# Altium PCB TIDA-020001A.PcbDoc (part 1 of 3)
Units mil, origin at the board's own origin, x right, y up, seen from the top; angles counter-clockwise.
Board outline 11050 x 5518 mil, 4 copper layers (Top Layer, PWR, GND, Bottom Layer), stack 61.434 mil thick; 283 components, 210 nets, 883 pads, 1184 vias.
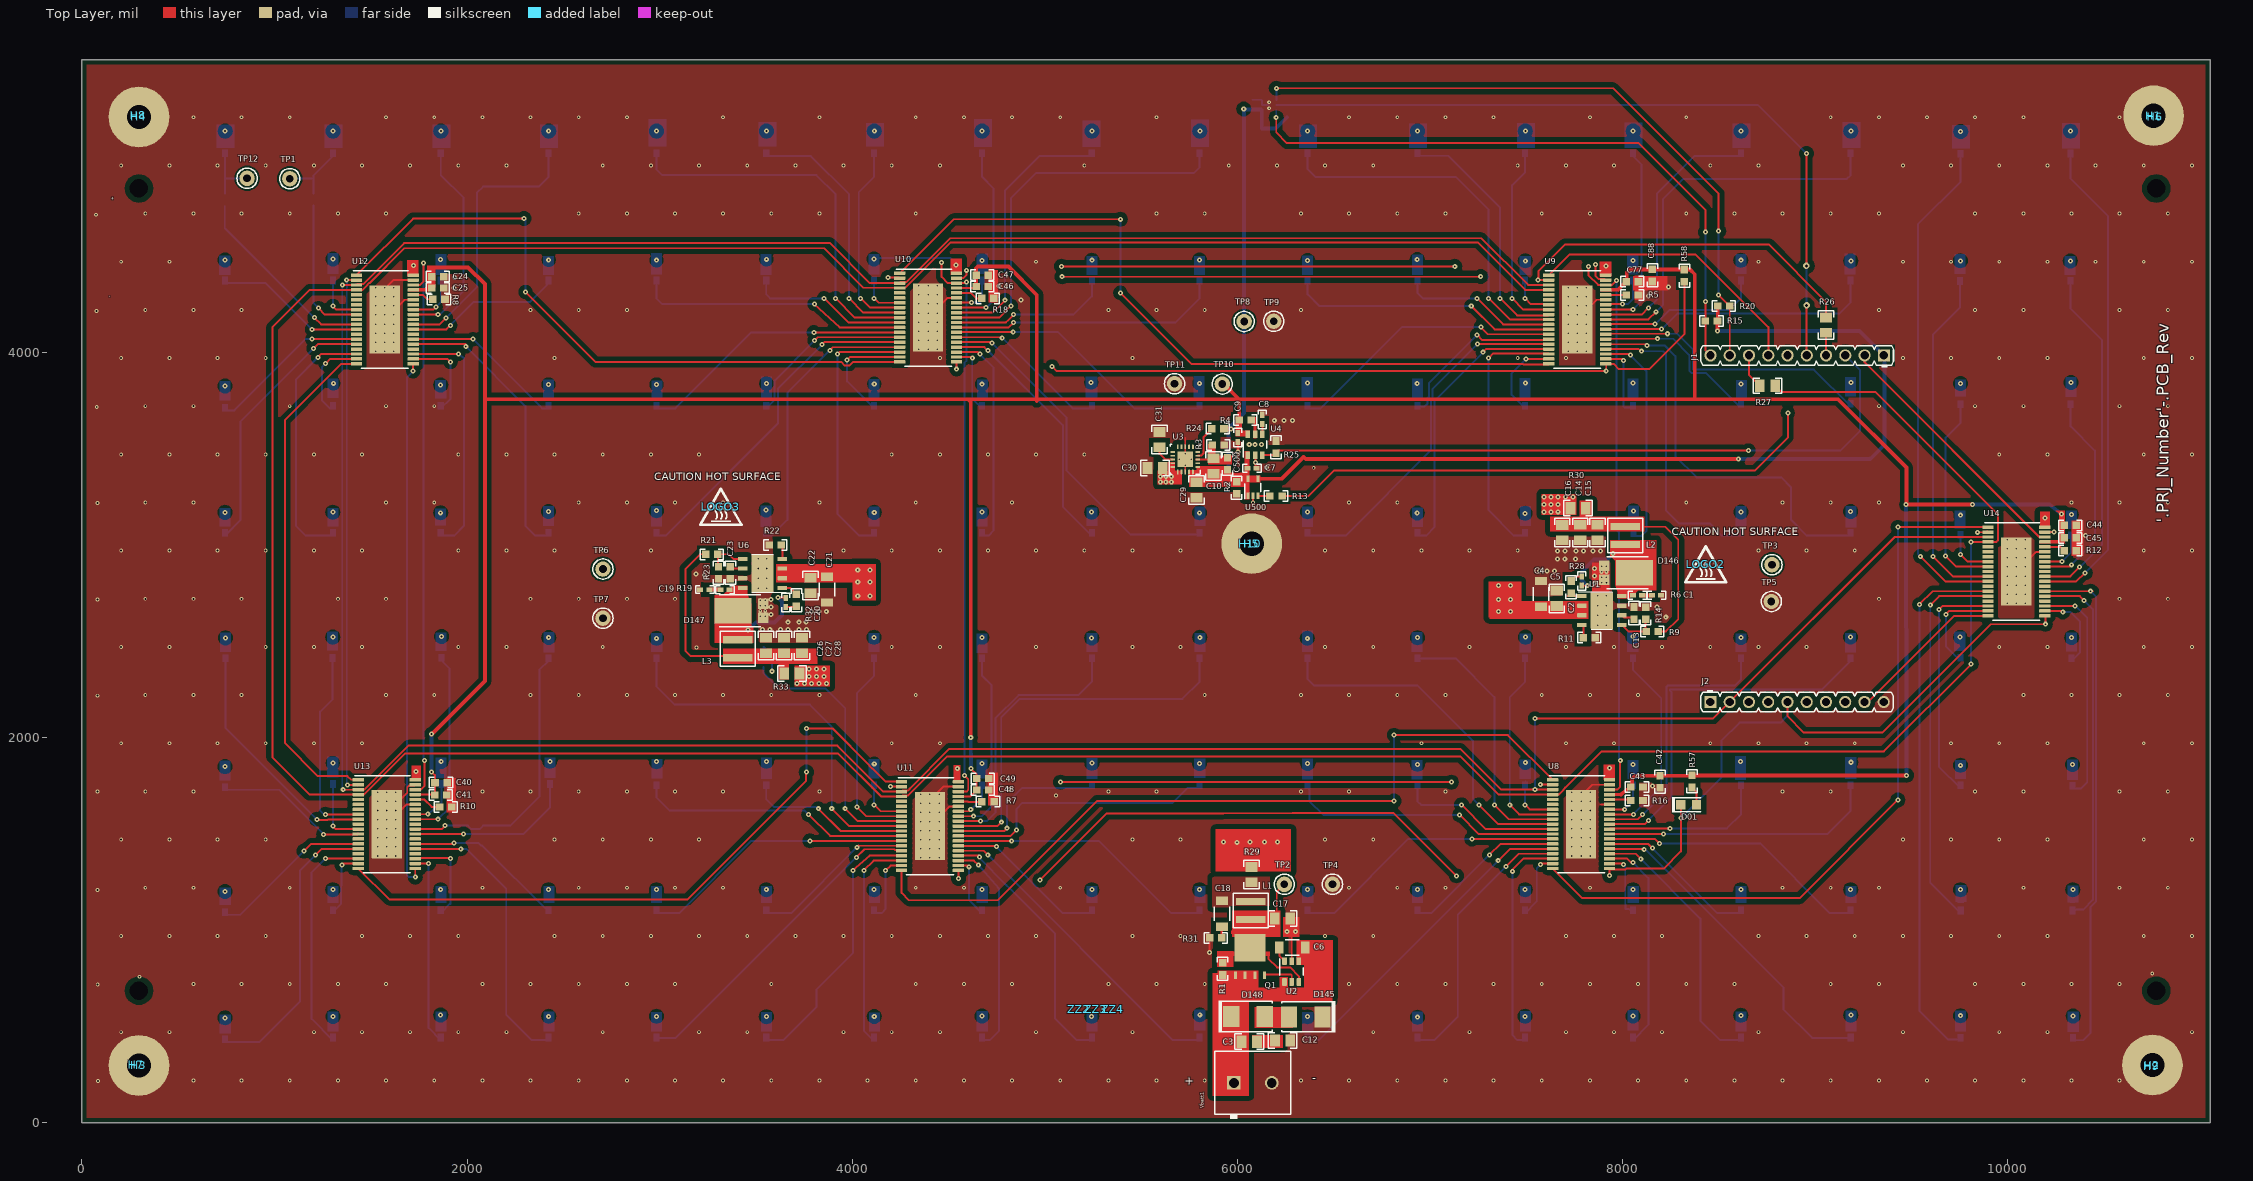
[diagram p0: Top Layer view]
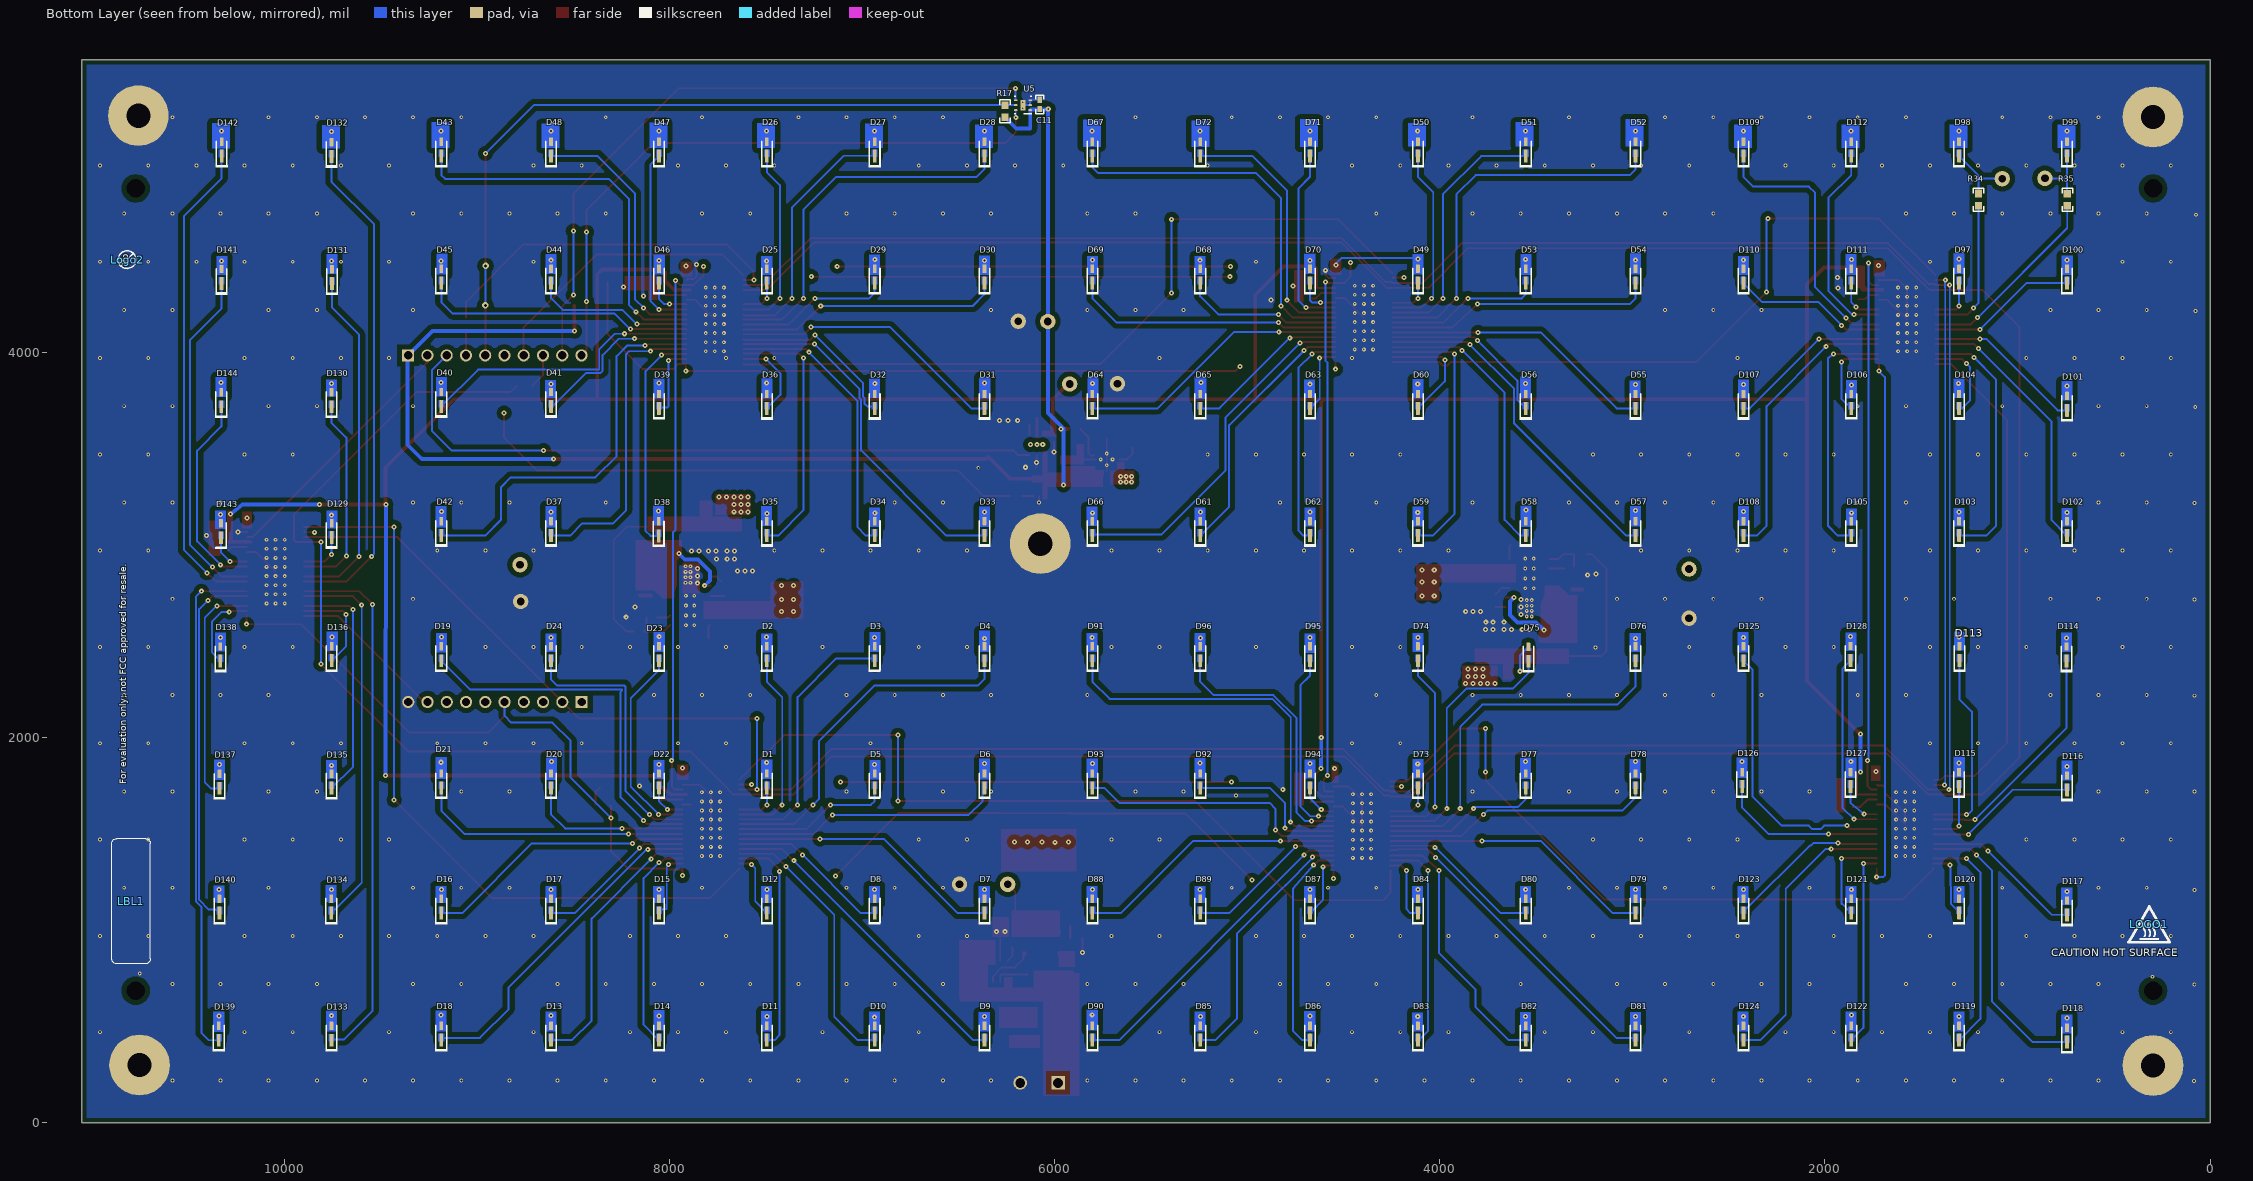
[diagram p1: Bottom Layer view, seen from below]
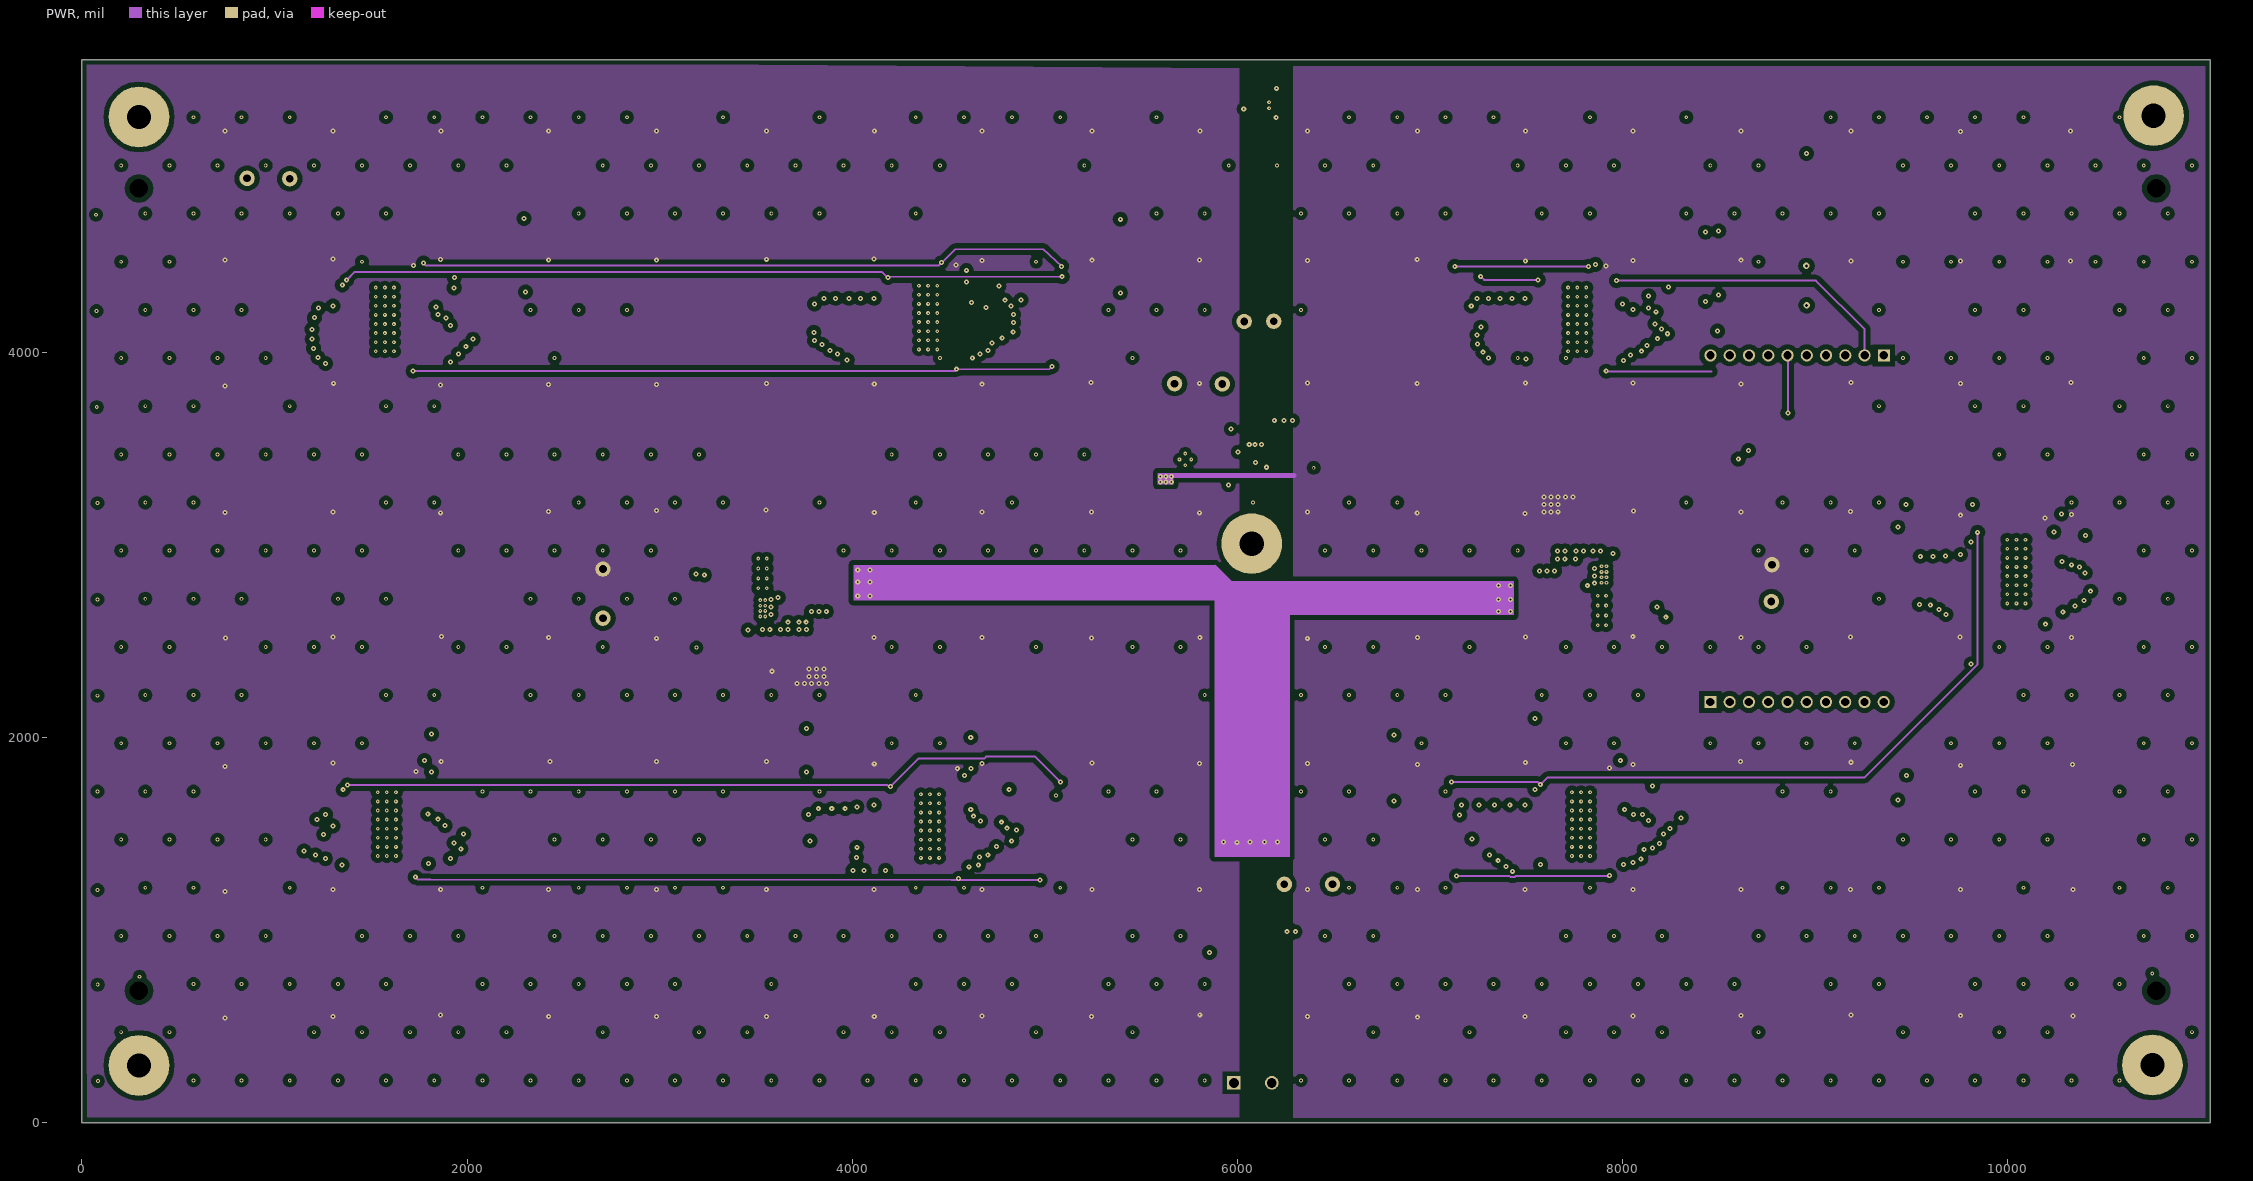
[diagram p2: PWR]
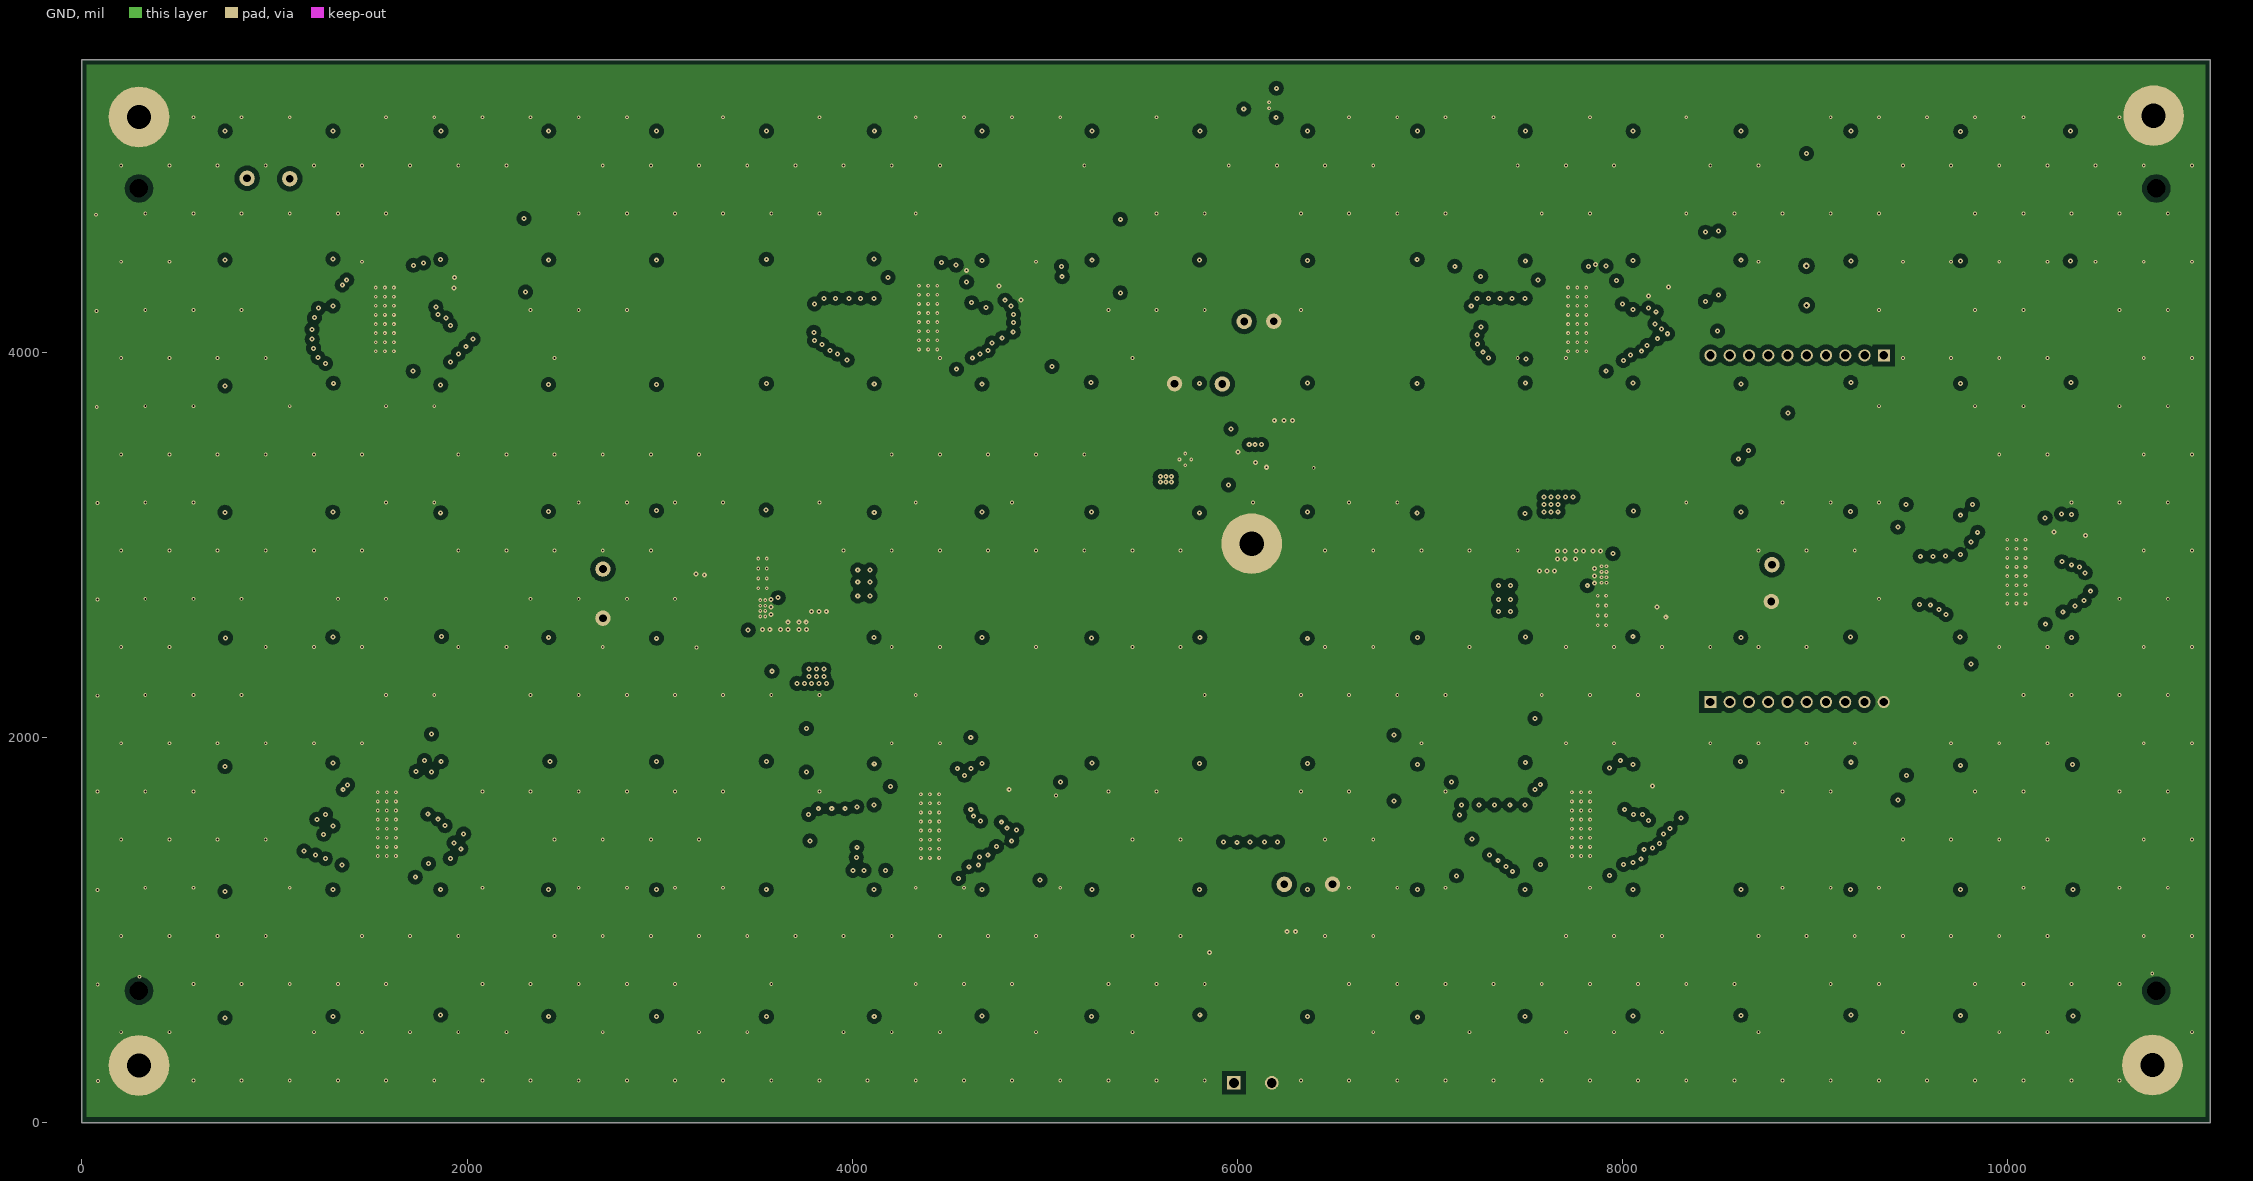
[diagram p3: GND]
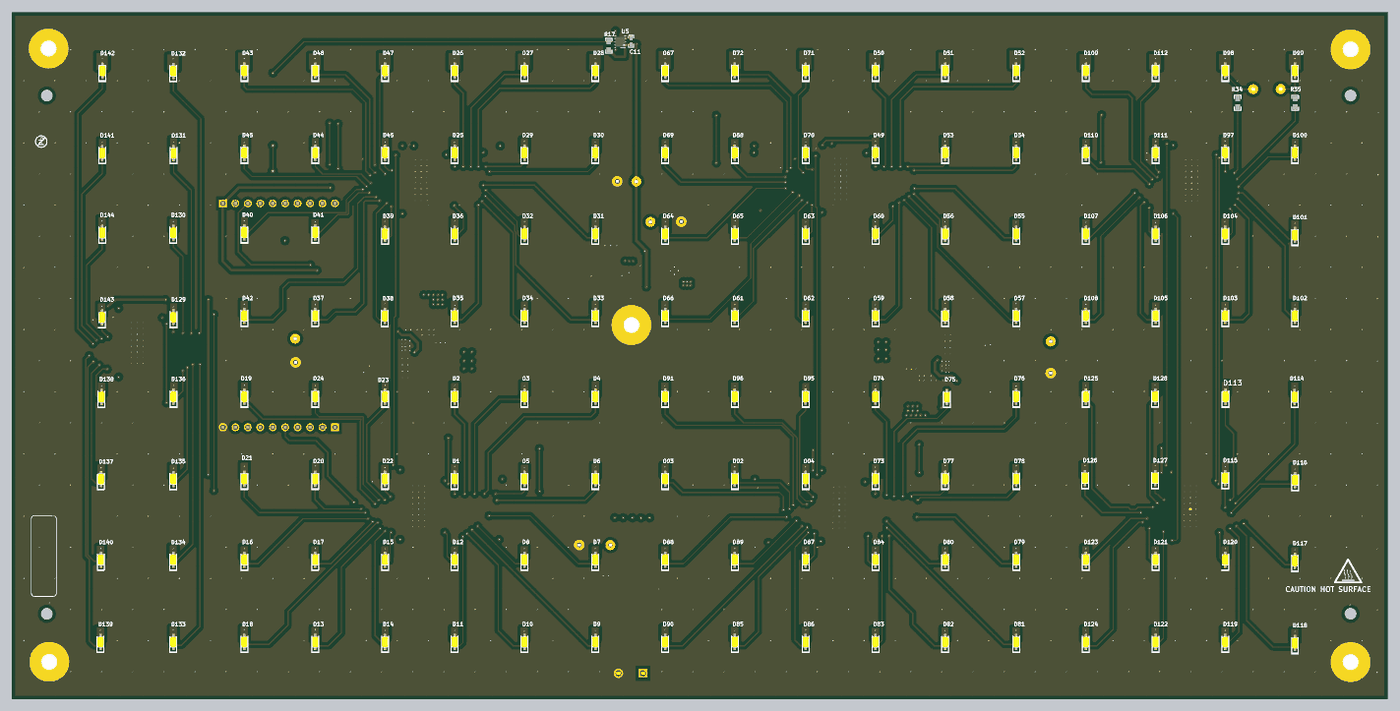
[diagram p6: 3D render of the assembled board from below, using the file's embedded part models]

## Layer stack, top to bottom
Top Solder: solder mask 0.4, Solder Resist, Dk 3.5
Top Layer: signal copper 1.4
Dielectric1: prepreg 18.6, 370HR, Dk 4.2
PWR: signal copper 1.417
Dielectric 2: core 18.6, 370HR, Dk 4.2
GND: signal copper 1.417
Dielectric 3: prepreg 18.6, 370HR, Dk 4.2
Bottom Layer: signal copper 1.4
Bottom Solder: solder mask 0.4, Solder Resist, Dk 3.5

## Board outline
0,0 11050,0 11050,5518 0,5518

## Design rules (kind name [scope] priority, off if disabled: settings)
AcuteAngle [All] p1: minimum=4.40000000000000E+0001 checktracksonly=FALSE
AssemblyTestPointUsage [All] p1: valid=2
BoardOutlineClearance BoardOutlineClearance_MountingHoles [OnCopper and InComponentClass('Mounting Holes')] p1: gap=40
BoardOutlineClearance BoardOutlineClearance_Poly [OnCopper and IsPoly] p2: gap=25
BoardOutlineClearance [OnCopper and Not InComponentClass('Logo') and not InComponentClass('FiducialMark') and not InRegion(1000,500,4000,800) and not InPoly] p3: gap=62.99
Clearance Clearance_Keepouts [((IsTrack Or IsArc) And Not InPoly) And IsFree and IsKeepOut vs ((IsTrack Or IsArc) And Not InPoly) And IsFree and IsKeepOut] p1: gap=0
Clearance Clearance_Poly [InPolygon] p2: gap=25
Clearance Clearance_FiducialMark [IsKeepOut and InComponentClass('FiducialMark') vs IsPad and InComponentClass('FiducialMark')] p3: gap=0
Clearance [All] p4: gap=7
ComponentClearance ComponentClearance_MountingHoles_FiducialMarks [InComponentClass('Mounting Holes') vs InComponentClass('FiducialMark')] p1: gap=0 collisioncheckmode=3 verticalgap=0 showdistances=TRUE
ComponentClearance ComponentClearance_Shunt [InComponentClass('Header') vs InComponentClass('Shunt')] p2: gap=0 collisioncheckmode=3 verticalgap=0 showdistances=FALSE
ComponentClearance ComponentClearance_Logo [InComponentClass('Logo')] p3: gap=50 collisioncheckmode=3 verticalgap=10 showdistances=FALSE
ComponentClearance ComponentClearance_ScrewToNut [(HasFootprint('NY PMS 440 0025 PH')) vs (HasFootprint('Keystone_1902C'))] p4: gap=5 collisioncheckmode=3 verticalgap=10 showdistances=FALSE
ComponentClearance ComponentClearance_MountingHoles [InComponentClass('Mounting Holes')] p5: gap=100 collisioncheckmode=3 verticalgap=100000 showdistances=FALSE
ComponentClearance ComponentClearance_SmallPassives [HasFootprint('0201*') or HasFootprint('0402*') or HasFootprint('0508') or HasFootprint('0603*') or HasFootprint('0612') or HasFootprint('0805*') or HasFootprint('0815*') or HasFootprint('0830*') or HasFootprint('1206*') or HasFootprint('1210*') or HasFootprint('1808*') or HasFootprint('1812*') or HasFootprint('1825*') or HasFootprint('2010*') or HasFootprint('2220*') or HasFootprint('2225*') or HasFootprint('2512*') or HasFootprint('2728*') or HasFootprint('3518*') vs HasFootprint('0201*') or HasFootprint('0402*') or HasFootprint('0508') or HasFootprint('0603*') or HasFootprint('0612') or HasFootprint('0805*') or HasFootprint('0815*') or HasFootprint('0830*') or HasFootprint('1206*') or HasFootprint('1210*') or HasFootprint('1808*') or HasFootprint('1812*') or HasFootprint('1825*') or HasFootprint('2010*') or HasFootprint('2220*') or HasFootprint('2225*') or HasFootprint('2512*') or HasFootprint('2728*') or HasFootprint('3518*')] p6: gap=14.96 collisioncheckmode=3 verticalgap=10 showdistances=FALSE
ComponentClearance ComponentClearance_THtoSMT [IsThruComponent vs IsSMTComponent] p7: gap=0 collisioncheckmode=3 verticalgap=0 showdistances=FALSE
ComponentClearance ComponentClearance_THtoTH [IsThruComponent vs IsThruComponent] p8: gap=30 collisioncheckmode=3 verticalgap=30 showdistances=FALSE
ComponentClearance [All] p9: gap=5 collisioncheckmode=3 verticalgap=5 showdistances=TRUE
DiffPairsRouting [All] p1: maxlimit=100 minlimit=10 mostfreqgap=10 toplayer_minwidth=15 toplayer_maxwidth=15 toplayer_prefwidth=15 midlayer1_minwidth=15 midlayer1_maxwidth=15 midlayer1_prefwidth=15 midlayer2_minwidth=15 midlayer2_maxwidth=15 midlayer2_prefwidth=15 bottomlayer_minwidth=15 bottomlayer_maxwidth=15 bottomlayer_prefwidth=15 maxuncoupledlength=1000
FabricationTestPointUsage TestPointUsage [All] p1: valid=2 allowmultiple=FALSE
FabricationTestpoint Testpoint [All] p1: side=3 testpointundercomponent=TRUE minsize=40 maxsize=100 preferedsize=60 minholesize=0 maxholesize=40 preferedholesize=32 testpointgrid=1 allowsidetop=TRUE allowsidebottom=TRUE usegrid=TRUE gridtolerance=0.01
FanoutControl Fanout_LCC [IsLCC] p1: bgadir=Out bgaviamode=Centered fanoutstyle=Auto fanoutdirection=Alternating viagrid=1 // Fanout_LCC (Default Rule)
FanoutControl Fanout_BGA [IsBGA] p2: bgadir=Out bgaviamode=Centered fanoutstyle=Auto fanoutdirection=Alternating viagrid=1 // Fanout_BGA (Default Rule)
FanoutControl Fanout_Default [All] p4: bgadir=Out bgaviamode=Centered fanoutstyle=Auto fanoutdirection=Alternating viagrid=1 // Fanout_Default (Default Rule)
FanoutControl Fanout_Small [(CompPinCount < 5)] p5: bgadir=Out bgaviamode=Centered fanoutstyle=Auto fanoutdirection=OutThenIn viagrid=1 // Fanout_Small (Default Rule)
HoleSize [All] p1: absolutevalues=TRUE maxlimit=251 minlimit=7.87 maxpercent=80.000 minpercent=20.000
MinimumAnnularRing MinimumAnnularRing_ThermalPadVias [IsVia and InAnyComponent] p1: minimumring=5.91
MinimumAnnularRing [All] p2: minimumring=5
MinimumSolderMaskSliver MinimumSolderMaskSliver_Logo [InComponentClass('Logo') vs InComponentClass('Logo')] p1: minsoldermaskwidth=0.7
MinimumSolderMaskSliver [All] p2: minsoldermaskwidth=3.94
PlaneConnect [All] p1: planeconnectstyle=Relief reliefexpansion=10 reliefentries=4 reliefconductorwidth=10 reliefairgap=10
PolygonConnect [All] p1: connectstyle=Direct reliefconductorwidth=10 reliefentries=4 polygonreliefangle="90 Angle" airgapwidth=10
RoutingVias ThermalPadVias [IsVia and InAnyComponent] p1: holewidth=7.87 width=19.68 viastyle="Through Hole" minholewidth=7.87 minwidth=19.68 maxholewidth=12.99 maxwidth=23.62
RoutingVias [All] p2: holewidth=16 width=34 viastyle="Through Hole" minholewidth=7.87 minwidth=20 maxholewidth=40 maxwidth=65
SilkToBoardRegionClearance [Not ((IsComment or IsDesignator) And (Hide <> 'False')) and not InRegion(1000,500,4000,800)] p1:
SilkToSilkClearance SilkToSilkClearance_Pb-FreeLogo [(HasFootprint('Pb-Free_Overlay_Medium') OR HasFootprint('Pb-Free_Overlay_Small')) vs (HasFootprint('Pb-Free_Overlay_Medium') OR HasFootprint('Pb-Free_Overlay_Small'))] p1 off: silktosilkclearance=0
SilkToSilkClearance [All] p2 off: silktosilkclearance=1
SilkToSolderMaskClearance SilkToComponentPadClearance [(IsPad or IsFill or IsRegion) and InAnycomponent] p1: minsilkscreentomaskgap=0.01 clearancetoexposedcopper=TRUE
SilkToSolderMaskClearance "Silk to Solder Mask Opening" [All] p2: minsilkscreentomaskgap=0.01 clearancetoexposedcopper=FALSE
SolderMaskExpansion [All] p1: expansion=1.97
Width [All] p1: maxlimit=100 minlimit=6 preferedwidth=10 checkconnectedcopper=TRUE
15 further rules are at their usual default settings.

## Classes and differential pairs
net class Undefined: 3V3 3V3_LS ANODE BLANK Buck1_4V ENABLE ERR GATE GCLK GND INT LATCH MISO MOSI NetC3_2 NetC6_2 NetC8_1 NetC10_2 NetC17_1 NetC31_1 NetD145_2 NetJ1_4 NetJ1_8 NetR4_1 NetR24_1 NetU2_17 NetU2_19 NetU3_2 NetU3_5 NetU3_6 NetU3_7 NetU3_9 NetU3_10 NetU3_11 NetU3_12 NetU7_1 NetU7_5 SCK SCLA SDAA Temp_Out
component class TIDA-020001A_TLC6C5724: C42 C43 C46 C47 C48 C49 C77 C88 D01 OUTR1/3 R5 R7 R16 R18 R57 R58 U8 U9 U10 U11
component class TIDA-020001A_TLC6C5716: C24 C25 C40 C41 C44 C45 R8 R10 R12 R34 R35 R? TP1 TP12 TP? U12 U13 U14
component class TIDA-020001A_OPT&C2000: C7 C8 C9 C10 C11 C29 C30 C31 C500 CFF1 CINL1 CNR/SS1 CoutL1 GND INTOPT1 J1 J2 R2 R3 R4 R13 R15 R17 R20 R24 R25 R26 R27 RPG1 SCLAOPT1 SDAAOPT1 TP8 TP9 TP10 TP11 U3 U4 U5 U500 VDD/Sense1 VinLDO1 VoutLDO1 VoutOPT1 VoutTemp1 VoutTPS1
component class TIDA-020001A_LEDs: D1 D2 D3 D4 D5 D6 D7 D8 D9 D10 D11 D12 D13 D14 D15 D16 D17 D18 D19 D20 D21 D22 D23 D24 D25 D26 D27 D28 D29 D30 D31 D32 D33 D34 D35 D36 D37 D38 D39 D40 D41 D42 D43 D44 D45 D46 D47 D48 D49 D50 D51 D52 D53 D54 D55 D56 D57 D58 D59 D60 D61 D62 D63 D64 D65 D66 D67 D68 D69 D70 D71 D72 D73 D74 D75 D76 D77 D78 D79 D80 D81 D82 D83 D84 D85 D86 D87 D88 D89 D90 D91 D92 D93 D94 D95 D96 D97 D98 D99 D100 D101 D102 D103 D104 D105 D106 D107 D108 D109 D110 D111 D112 D113 D114 D115 D116 D117 D118 D119 D120 D121 D122 D123 D124 D125 D126 D127 D128 D129 D130 D131 D132 D133 D134 D135 D136 D137 D138 D139 D140 D141 D142 D143 D144
component class Header: J1 J2
component class "Mounting Holes": H1 H2 H3 H4 H5
component class TIDA-020001A_Hardware: H1 H2 H3 H4 H5 H6 H7 H8 H9 H10 LBL1 LOGO1 LOGO2 Logo2 LOGO3 Logo3 LOGO? ZZ1 ZZ2 ZZ3 ZZ4
component class AssemblyNote: ZZ1 ZZ2 ZZ3 ZZ4
component class Label: LBL1
component class TIDA-020001A_LM74700&LMR14030: C1 C2 C3 C4 C5 C6 C12 C13 C14 C15 C16 C17 C18 C19 C20 C21 C22 C23 C26 C27 C28 D145 D146 D147 D148 GND L1 L2 L3 Q1 R1 R6 R9 R11 R14 R19 R21 R22 R23 R28 R29 R30 R31 R32 R33 TP2 TP3 TP4 TP5 TP6 TP7 U1 U2 U6 Vbatt1

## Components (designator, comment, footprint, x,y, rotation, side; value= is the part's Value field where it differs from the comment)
C1 "04025A101FAT2A" 0402 8175.5,2737.25 r0 top
C2 "GRM188R71C104KA01D" 0603 7732.28,2780.51 r90 top
C3 "08051A102JAT2A" 0805_HV 6061.02,420.28 r0 top
C4 "C3216X7R1H475K160AC" 1206_180 7575.79,2745.08 r90 top
C5 "C2012X5R1H104M085AA" 0805_HV 7657.48,2722.44 r270 top
C6 "C3216X7R2A105K160AA" 1206_180 6283.95,909.7 r180 top
C7 "C1005X5R1E105K050BC" 0402 6075.79,3397.64 r0 top
C8 "885012205044" 0402 6128.88,3651.62 r90 top
C9 "GMK105BJ104KV-F" 0402 6000.94,3557.3 r270 top
C10 "08055C103JAT2A" 0805_HV 5874.7,3408.47 r90 top
C11 "GMK105BJ104KV-F" 0402 6077.34,5287 r90 bottom
C12 "08051A102JAT2A" 0805_HV 6234.62,426.18 r0 top
C13 "C0603C223K5RACTU" 0603 8058.07,2645.67 r90 top
C14 "CL21B106KOQNNNE" 0805_HV 7779.53,3063.35 r270 top
C15 "CL21B106KOQNNNE" 0805_HV 7869.09,3063.98 r270 top
C16 "C0805C225K4RACTU" 0805_HV 7686.02,3062.99 r270 top
C17 "C2012X5R1H474K125AB" 0805_HV 6233.27,1059.06 r0 top
C18 "C3216X5R1V226M160AC" 1206_180 5919.29,1084.65 r270 top
C19 "04025A101FAT2A" 0402 3234.25,2767.72 r180 top
C20 "GRM188R71C104KA01D" 0603 3709.65,2712.6 r270 top
C21 "C3216X7R1H475K160AC" 1206_180 3869.09,2767.72 r270 top
C22 "C2012X5R1H104M085AA" 0805_HV 3782.48,2789.37 r90 top
C23 "C0603C223K5RACTU" 0603 3367.13,2855.31 r270 top
C24 "GRM188R61E106MA73D" 0603 1847.79,4391.67 r0 top
C25 "GRM188R61E106MA73D" 0603 1847.44,4333.66 r0 top
C26 "CL21B106KOQNNNE" 0805_HV 3551.93,2476.61 r90 top
C27 "CL21B106KOQNNNE" 0805_HV 3645.44,2477.6 r90 top
C28 "C0805C225K4RACTU" 0805_HV 3739.92,2477.6 r90 top
C29 "JMK212BJ226KG-T" 0805_HV 5787.93,3284.98 r270 top
C30 "GRM219R61E106KA12D" 0805_HV 5572.54,3398.27 r180 top
C31 "C2012X5R1H104M085AA" 0805_HV 5595.18,3545.91 r90 top
C40 "GRM188R61E106MA73D" 0603 1865.16,1764.76 r0 top
C41 "GRM188R61E106MA73D" 0603 1864.17,1700.79 r0 top
C42 "GRM188R61E106MA73D" 0603 8193.9,1769.68 r270 top
C43 "GRM188R61E106MA73D" 0603 8073.82,1742.13 r0 top
C44 "GRM188R61E106MA73D" 0603 10323.82,3101.38 r0 top
C45 "GRM188R61E106MA73D" 0603 10323.82,3036.42 r0 top
C46 "GRM188R61E106MA73D" 0603 4674.24,4340.56 r0 top
C47 "GRM188R61E106MA73D" 0603 4674.24,4399.62 r0 top
C48 "GRM188R61E106MA73D" 0603 4677.17,1726.38 r0 top
C49 "GRM188R61E106MA73D" 0603 4677.17,1786.42 r0 top
C77 "GRM188R61E106MA73D" 0603 8050.2,4366.14 r0 top
C88 "GRM188R61E106MA73D" 0603 8153.54,4398.62 r270 top
C500 "GRM188R71H104KA93D" 0603 5996.06,3296.26 r270 top
D01 "LTST-C170KRKT" LED_LTST-C170_Red 8342.52,1650.59 r180 top
D1 "" KW_DNLS31_RA_White 7493.56,1769.71 r90 bottom
D2 "" KW_DNLS31_RA_White 7493.56,2429.71 r90 bottom
D3 "" KW_DNLS31_RA_White 6933.56,2429.71 r90 bottom
D4 "" KW_DNLS31_RA_White 6363.56,2429.71 r90 bottom
D5 "" KW_DNLS31_RA_White 6933.56,1769.71 r90 bottom
D6 "" KW_DNLS31_RA_White 6363.56,1769.71 r90 bottom
D7 "" KW_DNLS31_RA_White 6363.56,1119.71 r90 bottom
D8 "" KW_DNLS31_RA_White 6933.56,1119.71 r90 bottom
D9 "" KW_DNLS31_RA_White 6363.56,459.71 r90 bottom
D10 "" KW_DNLS31_RA_White 6933.56,459.71 r90 bottom
D11 "" KW_DNLS31_RA_White 7493.56,459.71 r90 bottom
D12 "" KW_DNLS31_RA_White 7493.56,1119.71 r90 bottom
D13 "" KW_DNLS31_RA_White 8613.56,459.71 r90 bottom
D14 "" KW_DNLS31_RA_White 8053.56,459.71 r90 bottom
D15 "" KW_DNLS31_RA_White 8053.56,1119.71 r90 bottom
D16 "" KW_DNLS31_RA_White 9183.56,1119.71 r90 bottom
D17 "" KW_DNLS31_RA_White 8613.56,1119.71 r90 bottom
D18 "" KW_DNLS31_RA_White 9183.56,459.71 r90 bottom
D19 "" KW_DNLS31_RA_White 9183.56,2429.71 r90 bottom
D20 "" KW_DNLS31_RA_White 8613.56,1769.71 r90 bottom
D21 "" KW_DNLS31_RA_White 9183.56,1769.71 r90 bottom
D22 "" KW_DNLS31_RA_White 8053.56,1769.71 r90 bottom
D23 "" KW_DNLS31_RA_White 8053.56,2429.71 r90 bottom
D24 "" KW_DNLS31_RA_White 8613.56,2429.71 r90 bottom
D25 "" KW_DNLS31_RA_White 7493.56,4389.71 r90 bottom
D26 "" KW_DNLS31_RA_White 7493.56,5049.71 r90 bottom
D27 "" KW_DNLS31_RA_White 6933.56,5049.71 r90 bottom
D28 "" KW_DNLS31_RA_White 6363.56,5049.71 r90 bottom
D29 "" KW_DNLS31_RA_White 6933.56,4389.71 r90 bottom
D30 "" KW_DNLS31_RA_White 6363.56,4389.71 r90 bottom
D31 "" KW_DNLS31_RA_White 6363.56,3739.71 r90 bottom
D32 "" KW_DNLS31_RA_White 6933.56,3739.71 r90 bottom
D33 "" KW_DNLS31_RA_White 6363.56,3079.71 r90 bottom
D34 "" KW_DNLS31_RA_White 6933.56,3079.71 r90 bottom
D35 "" KW_DNLS31_RA_White 7493.56,3079.71 r90 bottom
D36 "" KW_DNLS31_RA_White 7493.56,3739.71 r90 bottom
D37 "" KW_DNLS31_RA_White 8613.56,3079.71 r90 bottom
D38 "" KW_DNLS31_RA_White 8054.9,3078.04 r90 bottom
D39 "" KW_DNLS31_RA_White 8053.56,3739.71 r90 bottom
D40 "" KW_DNLS31_RA_White 9183.56,3749.71 r90 bottom
D41 "" KW_DNLS31_RA_White 8613.56,3749.71 r90 bottom
D42 "" KW_DNLS31_RA_White 9183.56,3079.71 r90 bottom
D43 "" KW_DNLS31_RA_White 9183.56,5049.71 r90 bottom
D44 "" KW_DNLS31_RA_White 8613.56,4389.71 r90 bottom
D45 "" KW_DNLS31_RA_White 9183.56,4389.71 r90 bottom
D46 "" KW_DNLS31_RA_White 8053.56,4389.71 r90 bottom
D47 "" KW_DNLS31_RA_White 8053.56,5049.71 r90 bottom
D48 "" KW_DNLS31_RA_White 8613.56,5049.71 r90 bottom
D49 "" KW_DNLS31_RA_White 4113.56,4389.71 r90 bottom
D50 "" KW_DNLS31_RA_White 4113.56,5049.71 r90 bottom
D51 "" KW_DNLS31_RA_White 3553.56,5049.71 r90 bottom
D52 "" KW_DNLS31_RA_White 2983.56,5049.71 r90 bottom
D53 "" KW_DNLS31_RA_White 3553.56,4389.71 r90 bottom
D54 "" KW_DNLS31_RA_White 2983.56,4389.71 r90 bottom
D55 "" KW_DNLS31_RA_White 2983.56,3739.71 r90 bottom
D56 "" KW_DNLS31_RA_White 3553.56,3739.71 r90 bottom
D57 "" KW_DNLS31_RA_White 2983.56,3079.71 r90 bottom
D58 "" KW_DNLS31_RA_White 3553.56,3079.71 r90 bottom
D59 "" KW_DNLS31_RA_White 4113.56,3079.71 r90 bottom
D60 "" KW_DNLS31_RA_White 4113.56,3739.71 r90 bottom
D61 "" KW_DNLS31_RA_White 5243.56,3079.71 r90 bottom
D62 "" KW_DNLS31_RA_White 4673.56,3079.71 r90 bottom
D63 "" KW_DNLS31_RA_White 4673.56,3739.71 r90 bottom
D64 "" KW_DNLS31_RA_White 5803.56,3739.71 r90 bottom
D65 "" KW_DNLS31_RA_White 5243.56,3739.71 r90 bottom
D66 "" KW_DNLS31_RA_White 5803.56,3079.71 r90 bottom
D67 "" KW_DNLS31_RA_White 5803.56,5049.71 r90 bottom
D68 "" KW_DNLS31_RA_White 5243.56,4389.71 r90 bottom
D69 "" KW_DNLS31_RA_White 5803.56,4389.71 r90 bottom
D70 "" KW_DNLS31_RA_White 4673.56,4389.71 r90 bottom
D71 "" KW_DNLS31_RA_White 4673.56,5049.71 r90 bottom
D72 "" KW_DNLS31_RA_White 5243.56,5049.71 r90 bottom
D73 "" KW_DNLS31_RA_White 4113.56,1769.71 r90 bottom
D74 "" KW_DNLS31_RA_White 4113.56,2429.71 r90 bottom
D75 "" KW_DNLS31_RA_White 3539.78,2426.76 r90 bottom
D76 "" KW_DNLS31_RA_White 2983.56,2429.71 r90 bottom
D77 "" KW_DNLS31_RA_White 3553.56,1769.71 r90 bottom
D78 "" KW_DNLS31_RA_White 2983.56,1769.71 r90 bottom
D79 "" KW_DNLS31_RA_White 2983.56,1119.71 r90 bottom
D80 "" KW_DNLS31_RA_White 3553.56,1119.71 r90 bottom
D81 "" KW_DNLS31_RA_White 2983.56,459.71 r90 bottom
D82 "" KW_DNLS31_RA_White 3553.56,459.71 r90 bottom
D83 "" KW_DNLS31_RA_White 4113.56,459.71 r90 bottom
D84 "" KW_DNLS31_RA_White 4113.56,1119.71 r90 bottom
D85 "" KW_DNLS31_RA_White 5243.56,459.71 r90 bottom
D86 "" KW_DNLS31_RA_White 4673.56,459.71 r90 bottom
D87 "" KW_DNLS31_RA_White 4673.56,1119.71 r90 bottom
D88 "" KW_DNLS31_RA_White 5803.56,1119.71 r90 bottom
D89 "" KW_DNLS31_RA_White 5243.56,1119.71 r90 bottom
D90 "" KW_DNLS31_RA_White 5803.56,459.71 r90 bottom
D91 "" KW_DNLS31_RA_White 5803.56,2429.71 r90 bottom
D92 "" KW_DNLS31_RA_White 5243.56,1769.71 r90 bottom
D93 "" KW_DNLS31_RA_White 5803.56,1769.71 r90 bottom
D94 "" KW_DNLS31_RA_White 4673.56,1769.71 r90 bottom
D95 "" KW_DNLS31_RA_White 4673.56,2429.71 r90 bottom
D96 "" KW_DNLS31_RA_White 5243.56,2429.71 r90 bottom
D97 "" KW_DNLS31_RA_White 1303.56,4389.71 r90 bottom
D98 "" KW_DNLS31_RA_White 1303.56,5049.71 r90 bottom
D99 "" KW_DNLS31_RA_White 743.56,5049.71 r90 bottom
D100 "" KW_DNLS31_RA_White 743.56,4389.71 r90 bottom
D101 "" KW_DNLS31_RA_White 743.56,3729.71 r90 bottom
D102 "" KW_DNLS31_RA_White 743.56,3079.71 r90 bottom
D103 "" KW_DNLS31_RA_White 1303.56,3079.71 r90 bottom
D104 "" KW_DNLS31_RA_White 1303.56,3739.71 r90 bottom
D105 "" KW_DNLS31_RA_White 1863.56,3079.71 r90 bottom
D106 "" KW_DNLS31_RA_White 1863.56,3739.71 r90 bottom
D107 "" KW_DNLS31_RA_White 2423.56,3739.71 r90 bottom
D108 "" KW_DNLS31_RA_White 2423.56,3079.71 r90 bottom
D109 "" KW_DNLS31_RA_White 2423.56,5049.71 r90 bottom
D110 "" KW_DNLS31_RA_White 2423.56,4389.71 r90 bottom
D111 "" KW_DNLS31_RA_White 1863.56,4389.71 r90 bottom
D112 "" KW_DNLS31_RA_White 1863.56,5049.71 r90 bottom
D113 "" KW_DNLS31_RA_White 1302.17,2430.12 r90 bottom
D114 "" KW_DNLS31_RA_White 746,2428.61 r90 bottom
D115 "" KW_DNLS31_RA_White 1303.94,1776.01 r90 bottom
D116 "" KW_DNLS31_RA_White 743,1759 r90 bottom
D117 "" KW_DNLS31_RA_White 743.56,1109.71 r90 bottom
D118 "" KW_DNLS31_RA_White 743.56,449.71 r90 bottom
D119 "" KW_DNLS31_RA_White 1303.56,459.71 r90 bottom
D120 "" KW_DNLS31_RA_White 1303.56,1119.71 r90 bottom
D121 "" KW_DNLS31_RA_White 1863.56,1119.71 r90 bottom
D122 "" KW_DNLS31_RA_White 1863.56,459.71 r90 bottom
D123 "" KW_DNLS31_RA_White 2423.56,1119.71 r90 bottom
D124 "" KW_DNLS31_RA_White 2423.56,459.71 r90 bottom
D125 "" KW_DNLS31_RA_White 2423.56,2429.71 r90 bottom
D126 "" KW_DNLS31_RA_White 2429.93,1776.01 r90 bottom
D127 "" KW_DNLS31_RA_White 1866.94,1776.01 r90 bottom
D128 "" KW_DNLS31_RA_White 1866.84,2431.52 r90 bottom
D129 "" KW_DNLS31_RA_White 9752.68,3069.33 r90 bottom
D130 "" KW_DNLS31_RA_White 9753.68,3748.33 r90 bottom
D131 "" KW_DNLS31_RA_White 9751.68,4387.33 r90 bottom
D132 "" KW_DNLS31_RA_White 9753.68,5047.33 r90 bottom
D133 "" KW_DNLS31_RA_White 9753.68,459.33 r90 bottom
D134 "" KW_DNLS31_RA_White 9754.68,1119.33 r90 bottom
D135 "" KW_DNLS31_RA_White 9753.68,1768.33 r90 bottom
D136 "" KW_DNLS31_RA_White 9752.68,2430.33 r90 bottom
D137 "" KW_DNLS31_RA_White 10334.68,1767.33 r90 bottom
D138 "" KW_DNLS31_RA_White 10330.68,2428.33 r90 bottom
D139 "" KW_DNLS31_RA_White 10338.68,459.33 r90 bottom
D140 "" KW_DNLS31_RA_White 10335.68,1119.33 r90 bottom
D141 "" KW_DNLS31_RA_White 10324.68,4388.33 r90 bottom
D142 "" KW_DNLS31_RA_White 10323.68,5049.33 r90 bottom
D143 "" KW_DNLS31_RA_White 10327.68,3068.33 r90 bottom
D144 "" KW_DNLS31_RA_White 10325.68,3748.33 r90 bottom
D145 "SMBJ14A-13-F" SMB 6354.33,549.21 r180 top
D146 "PDS560-13" POWERDI5 7983.27,2855.31 r0 top
D147 "PDS560-13" POWERDI5 3458.66,2657.48 r180 top
D148 "SMBJ28A-13-F" SMB 6055.12,551.18 r0 top
H1 "NY PMS 440 0025 PH" "NY PMS 440 0025 PH" 10756,5228 r0 top
H2 "NY PMS 440 0025 PH" "NY PMS 440 0025 PH" 10750,299 r0 top
H3 "NY PMS 440 0025 PH" "NY PMS 440 0025 PH" 297,297 r0 top
H4 "NY PMS 440 0025 PH" "NY PMS 440 0025 PH" 297,5221 r0 top
H5 "NY PMS 440 0025 PH" "NY PMS 440 0025 PH" 6073.82,3005.91 r0 top
H6 "2205" KEYSTONE_2205 10763.78,5222.44 r0 top
H7 "2205" KEYSTONE_2205 283.46,301.18 r0 top
H8 "2205" KEYSTONE_2205 292.32,5231.3 r0 top
H9 "2205" KEYSTONE_2205 10746.06,292.32 r0 top
H10 "2205" KEYSTONE_2205 6064.96,3005.91 r0 top
J1 "61301011121" Wurth_61301011121 8905.68,3983.33 r180 top
J2 "61301011121" Wurth_61301011121 8905,2184 r0 top
L1 "XEL4030-102MEB" XEL4030_310 6068.9,1101.38 r90 top
L2 "XEL4030-152MEB" XEL4030_320 8013.78,3048.21 r90 top
L3 "XEL4030-152MEB" XEL4030_320 3405.51,2460.24 r270 top
LBL1 "THT-14-423-10" Label_650x200 10794,1150 r90 bottom
LOGO1 "CAUTION HOT SURFACE" IEC_HotSurface_Small 316.93,1029.53 r180 bottom
LOGO2 "CAUTION HOT SURFACE" IEC_HotSurface_Small 8431.1,2898.62 r0 top
Logo2 "Pb-Free Symbol" Pb-Free_Overlay_Small 10814.96,4480.31 r90 bottom
LOGO3 "CAUTION HOT SURFACE" IEC_HotSurface_Small 3317.91,3197.83 r0 top
Logo3 "FCC disclaimer" FCC_disclaimer 21656,408 r90 bottom
Q1 "SQJ412EP-T1-GE3" PowerPAK_SO-8L 6064.95,875.7 r90 top
R1 "CRCW06030000Z0EA" 0603 5923.23,798.23 r90 top
R2 "CRCW060311K8FKEA" 0603 5948.82,3421.26 r270 top
R3 "RG1608P-3741-B-T5" 0603 5900.7,3518.47 r180 top
R4 "RG1608P-511-B-T5" 0603 6040.94,3647.3 r180 top
R5 "CRCW06031K60JNEA" 0603 8050.2,4297.24 r180 top
R6 "CRCW040210R0JNED" 0402 8077.76,2737.2 r0 top
R7 "CRCW06031K60JNEA" 0603 4704.72,1666.34 r180 top
R8 "CRCW06031K60JNEA" 0603 1854.33,4274.61 r180 top
R9 "CRCW0603100KFKEA" 0603 8153.54,2550.2 r180 top
R10 "CRCW06031K60JNEA" 0603 1888.78,1638.78 r180 top
R11 "CRCW060310K0FKEA" 0603 7826.77,2517.72 r180 top
R12 "CRCW06031K60JNEA" 0603 10323.82,2969.49 r180 top
R13 "RC0603FR-07100RL" 0603 6199.8,3253.94 r0 top
R14 "RC0603FR-0723K2L" 0603 8119.09,2644.69 r270 top
R15 "RC0603FR-074K7L" 0603 8460.63,4162.4 r0 top
R16 "CRCW06031K60JNEA" 0603 8073.82,1672.24 r180 top
R17 "RMCF0603FT10K0" 0603 6256.97,5251.17 r270 bottom
R18 "CRCW06031K60JNEA" 0603 4703.74,4279.53 r180 top
R19 "CRCW040210R0JNED" 0402 3338.58,2766.73 r180 top
R20 "RC0603FR-074K7L" 0603 8524.61,4239.17 r180 top
R21 "CRCW0603100KFKEA" 0603 3270.67,2950.79 r0 top
R22 "CRCW060310K0FKEA" 0603 3600.09,2998.79 r0 top
R23 "RC0603FR-0723K2L" 0603 3305.42,2855.54 r90 top
R24 "RMCF0603FT10K0" 0603 5898.36,3602.5 r0 top
R25 "RMCF0603FT10K0" 0603 6199.94,3507.3 r270 top
R26 "CRCW08050000Z0EA" 0805_HV 9055.92,4140.3 r270 top
R27 "CRCW08050000Z0EA" 0805_HV 8750.98,3825.79 r180 top
R28 "CRCW04023R30JNED" 0402 7786.42,2812.01 r270 top
R29 "CRCW08050000Z0EA" 0805_HV 6071.85,1287.4 r90 top
R30 "CRCW08050000Z0EA" 0805_HV 7768.7,3189.96 r180 top
R31 "ERJ-3RQFR33V" 0603 5886.81,959.65 r0 top
R32 "CRCW04023R30JNED" 0402 3654.53,2700.79 r90 top
R33 "CRCW08050000Z0EA" 0805_HV 3686.04,2332.68 r0 top
R34 "CRCW06030000Z0EA" 0603 1203.74,4792.32 r90 bottom
R35 "CRCW06030000Z0EA" 0603 742.13,4791.34 r90 bottom
R57 "RNCF0603TKY1K00" 0603 8359.25,1771.65 r90 top
R58 "RC0603FR-073K3L" 0603 8319.88,4397.64 r90 top
TP1 "5000" Keystone5004 1079.72,4900.59 r90 top
TP2 "5000" Keystone5000 6243.11,1237.2 r90 top
TP3 "5000" Keystone5000 8774.61,2896.65 r90 top
TP4 "5001" Keystone5001 6493.11,1238.19 r90 top
TP5 "5001" Keystone5001 8771.65,2705.71 r90 top
TP6 "5000" Keystone5000 2705.71,2874.02 r90 top
TP7 "5001" Keystone5001 2705.71,2619.09 r90 top
TP8 "5000" Keystone5000 6034.45,4159.45 r90 top
TP9 "5001" Keystone5001 6187.99,4160.43 r90 top
TP10 "5000" Keystone5000 5921.26,3834.65 r90 top
TP11 "5001" Keystone5001 5673.23,3836.61 r90 top
TP12 "5000" Keystone5004 858.27,4902.56 r90 top
U1 "LMR14030SQDDARQ1" DDA0008E_L 7891.73,2658.86 r0 top
U2 "LM74700QDBVRQ1" DBV0006A_N#1 6281.5,784.45 r270 top
U3 "TPS7A5201QRGRRQ1" RGR0020A 5728.93,3442.98 r180 top
U4 "TPS22918QDBVRQ1" DBV0006A_N#2 6091.8,3519.55 r90 top
U5 "OPT3001IDNPRQ1" DNP0006A 6163.63,5282.24 r0 bottom
U6 "LMR14030SQDDARQ1" DDA0008E_L 3534.15,2851.35 r180 top
U8 "TLC6C5724QDAPRQ1" DAP0038E 7783.56,1549.71 r0 top
U9 "TLC6C5724QDAPRQ1" DAP0038E 7763.56,4169.71 r0 top
U10 "TLC6C5724QDAPRQ1" DAP0038E 4393.56,4179.71 r0 top
U11 "TLC6C5724QDAPRQ1" DAP0038E 4403.56,1539.71 r0 top
U12 "TLC6C5716QDAPRQ1" DAP0038E 1573.56,4169.71 r0 top
U13 "TLC6C5716QDAPRQ1" DAP0038E 1583.56,1549.71 r0 top
U14 "TLC6C5716QDAPRQ1" DAP0038E 10043.68,2861.33 r0 top
U500 "LMT87QDCKRQ1" DCK0005A_N 6080.71,3298.23 r90 top
Vbatt1 "691213710002" Wurth_691213710002 6079.72,206.69 r0 top
ZZ1 "This Assembly Note is for PCB labels only" AssemblyNoteLabel -73.82,7469.49 r0 top
ZZ2 "These assemblies are ESD sensitive, ESD precautions shall be observed." AssemblyNote 5176.24,589.02 r90 top
ZZ3 "These assemblies must be clean and free from flux and all contaminants. Use of no clean flux is not acceptable." AssemblyNote 5264.8,589.02 r90 top
ZZ4 "These assemblies must comply with workmanship standards IPC-A-610 Class 2, unless otherwise specified." AssemblyNote 5353.35,589.02 r90 top

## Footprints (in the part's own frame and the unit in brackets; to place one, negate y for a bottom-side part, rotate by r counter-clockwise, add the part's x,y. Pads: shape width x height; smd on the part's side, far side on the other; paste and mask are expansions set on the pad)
0402 [mm] "0402 from SM-752 data"
  rect 0.8x0.6 smd: 1(-0.6,0) 2(0.6,0)
  silkscreen extent -1.22,-0.52 1.22,0.52, body extent -0.55,-0.3 0.55,0.3, height 0.6
0603 [mm] "0603 from SM-752 data"
  rect 1x0.95 smd: 1(-0.8,0) 2(0.8,0)
  silkscreen extent -1.52,-0.69 1.52,0.69, body extent -0.87,-0.47 0.87,0.47, height 1
0805_HV [mil] "0805 with 30mil clearance between pads"
  rect 50x63 smd: 1(-40,0) 2(40,0)
  silkscreen extent -74,-40 74,40, body extent -43,-29 43,29, height 57
1206_180 [mm] "1206_180"
  rect 1.1x1.6 smd: 1(-1.7,0) 2(1.7,0)
  silkscreen extent -0.9,-1 0.9,1, body extent -1.75,-0.95 1.75,0.95, height 1.8
AssemblyNote [mil] "Assembly Note"
AssemblyNoteLabel [mil] "Assembly Note for PCB Labels"
DAP0038E [mm] "SOP, 38-Leads, Body 6.1x12.5mm, Pitch 0.65mm"
  rrect22% 1.5x0.45 smd: 1(-3.75,5.85) 2(-3.75,5.2) 3(-3.75,4.55) 4(-3.75,3.9) 5(-3.75,3.25) 6(-3.75,2.6) 7(-3.75,1.95) 8(-3.75,1.3) 9(-3.75,0.65) 10(-3.75,0) 11(-3.75,-0.65) 12(-3.75,-1.3) 13(-3.75,-1.95) 14(-3.75,-2.6) 15(-3.75,-3.25) 16(-3.75,-3.9) 17(-3.75,-4.55) 18(-3.75,-5.2) 19(-3.75,-5.85) 20(3.75,-5.85) 21(3.75,-5.2) 22(3.75,-4.55) 23(3.75,-3.9) 24(3.75,-3.25) 25(3.75,-2.6) 26(3.75,-1.95) 27(3.75,-1.3) 28(3.75,-0.65) 29(3.75,0) 30(3.75,0.65) 31(3.75,1.3) 32(3.75,1.95) 33(3.75,2.6) 34(3.75,3.25) 35(3.75,3.9) 36(3.75,4.55) 37(3.75,5.2) 38(3.75,5.85)
  rrect2% 4x9 smd paste-9 mask-4: 39(0,0)
  rrect12% 0.8x1.178 on Top Paste: ""(0,-2.059) ""(0,2.059)
  rrect5% 1.94x2.54 on Top Paste: ""(0,0)
  silkscreen extent -4.2,-6.4 3.1,6.4, body extent -4.05,-6.25 4.05,6.25, height 1.13
DBV0006A_N#1 [mm] "SOT23, 6-Leads, Body 2.9x1.6mm, Pitch 0.95mm, Lead Span 2.8mm, IPC Medium Density"
  rrect17% 1x0.6 smd: 1(-1.375,-0.95) 2(-1.375,0) 3(-1.375,0.95) 4(1.375,0.95) 5(1.375,0) 6(1.375,-0.95)
  silkscreen extent -1.67,-1.55 0.5,1.55, body extent -1.42,-1.46 1.42,1.46, height 1.73
DBV0006A_N#2 [mm] "SOT23, 6-Leads, Body 2.9x1.6mm, Pitch 0.95mm, Lead Span 2.8mm, IPC Medium Density"
  rrect17% 1x0.6 smd: 1(-1.375,0.95) 2(-1.375,0) 3(-1.375,-0.95) 4(1.375,-0.95) 5(1.375,0) 6(1.375,0.95)
  silkscreen extent -1.67,-1.55 0.5,1.55, body extent -1.42,-1.46 1.42,1.46, height 1.12
DCK0005A_N [mm] "SOT353, 5-Leads, Body 2x1.3mm, Pitch 0.65mm, Lead Span 2.1mm, IPC Medium Density"
  rrect25% 0.85x0.4 smd: 1(-1.125,0.65) 2(-1.125,0) 3(-1.125,-0.65) 4(1.125,-0.65) 5(1.125,0.65)
  silkscreen extent -1.48,-1.02 0.55,1.1, body extent -1.14,-1 1.14,1, height 0.95
DDA0008E_L [mm]
  rrect18% 1.25x0.55 smd: 1(-2.625,1.905) 2(-2.625,0.635) 3(-2.625,-0.635) 4(-2.625,-1.905) 5(2.625,-1.905) 6(2.625,-0.635) 7(2.625,0.635) 8(2.625,1.905)
  rrect7% 2.95x4.9 smd paste-1.5 mask-1.5: 9(0,0)
  rrect4% 2.4x3.1 on Top Paste: 9(0,0)
  rrect4% 2.4x3.1 on Top Solder: 9(0,0)
  silkscreen extent -3.13,-2.5 1.4,2.5, body extent -3,-2.45 3,2.45, height 1.57
DNP0006A [mm] "DFN-6 2x2mm"
  oval 0.5x0.25 smd: 1(-0.95,0.65) 2(-0.95,0) 3(-0.95,-0.655) 4(0.95,-0.65) 5(0.95,0) 6(0.95,0.65)
  rect 0.65x1.35 smd paste-0.5: 7(0,0)
  silkscreen extent -1.12,-1.15 1.12,1.15, body extent -1,-1 1,1, height 0.64
FCC_disclaimer [mil]
IEC_HotSurface_Small [mil]
  silkscreen extent -107,-93 107,92
Keystone5000 [mil] "For Keystone 500x miniature loop terminals"
  round 80 hole 40: 1(0,0)
  silkscreen extent -52,-52 52,52, body extent -49,-49 49,49, height 182
Keystone5001 [mil] "For Keystone 500x miniature loop terminals"
  round 80 hole 40: 1(0,0)
  silkscreen extent -52,-52 52,52, body extent -49,-49 49,49, height 182
Keystone5004 [mil] "For Keystone 500x miniature loop terminals"
  round 80 hole 40: 1(0,0)
  silkscreen extent -52,-52 52,52, body extent -49,-49 49,49, height 182
KEYSTONE_2205 [mil] "THREAD HEX ALUMINUM STANDOFF 4-40, F-F 1\""
  round 1 on Mech3: 0(0,0)
  body extent -148,-128 148,128, height 1001
KW_DNLS31_RA_White [mm] "SMD, 2-Leads, Body 2.3x1.4mm"
  rrect20% 1.7x0.5 smd paste-0.05 mask+0: 1(-0.8,0)
  rrect20% 1.1x0.5 smd paste-0.05 mask+0: 2(1.1,0)
  Top Layer region: 0.551,0.4 0.951,0.4 0.951,-0.4 0.551,-0.4
  Top Layer region: -0.949,0.4 0.051,0.4 0.051,-0.4 -0.949,-0.4
  silkscreen extent -2.3,-0.8 1.15,0.8, body extent -1.15,-0.7 1.15,0.7, height 0.75
Label_650x200 [mil] "Thermal Transfer Label"
  round 1 on Mech14: 0(0,0)
  silkscreen extent -325,-100 325,100, body extent -325,-100 325,100, height 1
LED_LTST-C170_Red [mm] "LITE-ON"
  rect 1.2x1.2 smd: 1(-1.05,0) 2(1.05,0)
  silkscreen extent -1.6,-1 2.2,1, body extent -1.05,-0.67 1.05,0.67, height 1.1
"NY PMS 440 0025 PH" [mm] "4-40 nylon screw and mounting hole"
  round 8 hole 3.2: 1(0,0)
  body extent -3.3,-3.3 3.3,3.3, height 2.69
Pb-Free_Overlay_Small [mil]
  silkscreen extent -46,-46 46,46
POWERDI5 [mm] "Diodes Inc recommended land pattern, ap02001.pdf rev 60"
  rect 1.4x1.39 smd: 1(-1.991,0.92) 2(-1.991,-0.92)
  rect 4.86x3.36 smd: 3(1.991,0)
  silkscreen extent -1.7,-2.1 3.8,2.1, body extent -2.27,-2.03 4.33,2.03, height 1.17
PowerPAK_SO-8L [mm] "based on Vishay recommended land pattern Document 63818 Feb 7, 2012"
  rect 1x0.41 smd: 1(-2.805,1.905) 2(-2.805,0.635) 3(-2.805,-0.635) 4(-2.805,-1.905)
  rect 3.63x4.061 smd: 5(0.805,0)
  Top Layer region: 2.614,-2.5 3.124,-2.5 3.124,2.5 2.614,2.5
  Top Layer region: -0.298,2.03 0.297,2.03 0.297,2.64 -0.298,2.64
  Top Layer region: -0.298,-2.64 0.297,-2.64 0.297,-2.03 -0.298,-2.03
  body extent -3.07,-2.57 3.08,2.57, height 1.21
RGR0020A [mm] "QFN, 20-Leads, Body 3.5x3.5mm, Pitch 0.5mm, Thermal Pad 2.05x2.05mm, TI Recommended"
  rrect42% 0.6x0.24 smd: 1(-1.65,1) 2(-1.65,0.5) 3(-1.65,0) 4(-1.65,-0.5) 5(-1.65,-1) 11(1.65,-1) 12(1.65,-0.5) 13(1.65,0) 14(1.65,0.5) 15(1.65,1)
  rrect42% 0.24x0.6 smd: 6(-1,-1.65) 7(-0.5,-1.65) 8(0,-1.65) 9(0.5,-1.65) 10(1,-1.65) 16(1,1.65) 17(0.5,1.65) 18(0,1.65) 19(-0.5,1.65) 20(-1,1.65)
  rrect5% 2.05x2.05 smd paste-1.025: 21(0,0)
  silkscreen extent -1.97,-1.97 1.97,1.97, body extent -1.75,-1.75 1.75,1.75, height 1
SMB [mil] "Molded Diode, 2-Leads, Body 5.4x3.6mm, IPC Medium Density, based on OnSemi component dimensions"
  rect 85x107.99 smd: 1(-87.01,0) 2(87.01,0)
  silkscreen extent -155,-82 125,82, body extent -106,-71 106,71, height 91
Wurth_61301011121 [mm] "Header, 2.54mm, 10x1, TH"
  rect 1.6x1.6 hole 1.1: 1(-11.43,0)
  round 1.6 hole 1.1: 2(-8.89,0) 3(-6.35,0) 4(-3.81,0) 5(-1.27,0) 6(1.27,0) 7(3.81,0) 8(6.35,0) 9(8.89,0) 10(11.43,0)
  silkscreen extent -12.7,-1.27 12.7,1.6, body extent -12.7,-1.27 12.7,1.27, height 8.54
Wurth_691213710002 [mm] "TH, 2-Leads, Body 10x8.3mm, Pitch 5mm"
  rect 1.8x1.8 hole 1.3: 1(-2.5,0)
  round 1.8 hole 1.3: 2(2.5,0)
  silkscreen extent -5,-4.75 5,4.15, body extent -5.6,-4.15 5,4.15, height 10
XEL4030_310 [mm] "SMD, 2-Leads, Body 4x4mm, Pitch 2.37mm"
  rect 0.98x3.9 smd: 1(-1.185,0) 2(1.185,0)
  silkscreen extent -2.3,-2.3 2.3,2.3, body extent -2.15,-2.15 2.15,2.15, height 3.1
XEL4030_320 [mm] "SMD, 2-Leads, Body 4x4mm, Pitch 2.37mm"
  rect 0.98x3.9 smd: 1(-1.185,0) 2(1.185,0)
  silkscreen extent -2.3,-2.3 2.3,2.3, body extent -2.15,-2.15 2.15,2.15, height 3.2

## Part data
C1 C19: library part CMP-0006196-2, "CAP, CERM, 100 pF, 50 V, +/- 1%, C0G/NP0, 0402"
C2 C20: "CAP, CERM, 0.1 µF, 16 V, +/- 10%, X7R, 0603"
C3 C12: "CAP, CERM, 1000 pF, 100 V, +/- 5%, C0G/NP0, 0805"
C4 C21: library part CMP-0008702-2, "CAP, CERM, 4.7 uF, 50 V, +/- 10%, X7R, 1206"
C5 C22 C31: "CAP, CERM, 0.1 µF, 50 V,+/- 20%, X5R, 0805"
C6: "CAP, CERM, 1 µF, 100 V, +/- 10%, X7R, 1206"
C7: "CAP, CERM, 1 µF, 25 V,+/- 10%, X5R, 0402"
C8: "CAP, CERM, 1000 pF, 25 V,+/- 10%, X7R, 0402"
C9 C11: "CAP, CERM, 0.1 µF, 35 V,+/- 10%, X5R, 0402"
C10: "CAP, CERM, 0.01 µF, 50 V,+/- 5%, X7R, 0805"
C13 C23: library part CMP-0006901-4, "CAP, CERM, 0.022 uF, 50 V, +/- 10%, X7R, 0603"
C14 C15 C26 C27: library part CMP-0007995-2, "CAP, CERM, 10 uF, 16 V, +/- 10%, X7R, 0805"
C16 C28: library part CMP-0007770-2, "CAP, CERM, 2.2 uF, 16 V, +/- 10%, X7R, 0805"
C17: library part CMP-0007839-2, "CAP, CERM, 0.47 uF, 50 V, +/- 10%, X5R, 0805"
C18: library part CMP-0008667-2, "CAP, CERM, 22 uF, 35 V, +/- 20%, X5R, 1206"
C24 C25 C40 C41 C42 C43 C44 C45 C46 C47 C48 C49 C77 C88: "CAP, CERM, 10 µF, 25 V, +/- 20%, X5R, 0603"
C29: "CAP, CERM, 22 µF, 6.3 V,+/- 10%, X5R, 0805"
C30: "CAP, CERM, 10 µF, 25 V,+/- 10%, X5R, 0805"
C500: "CAP, CERM, 0.1 µF, 50 V,+/- 10%, X7R, 0603"
D01: library part CMP-0002829-2, "LED, Red, SMD"
D1 D2 D3 D4 D5 D6 D7 D8 D9 D10 D11 D12 D13 D14 D15 D16 D17 D18 D19 D20 D21 D22 D23 D24 D25 D26 D27 D28 D29 D30 D31 D32 D33 D34 D35 D36 D37 D38 D39 D40 D41 D42 D43 D44 D45 D46 D47 D48 D49 D50 D51 D52 D53 D54 D55 D56 D57 D58 D59 D60 D61 D62 D63 D64 D65 D66 D67 D68 D69 D70 D71 D72 D73 D74 D75 D76 D77 D78 D79 D80 D81 D82 D83 D84 D85 D86 D87 D88 D89 D90 D91 D92 D93 D94 D95 D96 D97 D98 D99 D100 D101 D102 D103 D104 D105 D106 D107 D108 D109 D110 D111 D112 D113 D114 D115 D116 D117 D118 D119 D120 D121 D122 D123 D124 D125 D126 D127 D128 D129 D130 D131 D132 D133 D134 D135 D136 D137 D138 D139 D140 D141 D142 D143 D144: library part CMP-0078618-1, "LED, White, SMD"
D145: "Diode, TVS, Uni, 14 V, 600 W, SMB"
D146 D147: library part CMP-0028523-1, "Diode, Schottky, 60 V, 5 A, PowerDI5"
D148: "Diode, TVS, Uni, 28 V, 600 W, SMB"
H1 H2 H3 H4 H5: "Machine Screw, Round, #4-40 x 1/4, Nylon, Philips panhead"
H6 H7 H8 H9 H10: "Standoff, Hex, 1\"L #4-40 Aluminum"
J1 J2: library part CMP-0054804-1, "Header, 2.54mm, 10x1, Gold, TH"
L1: library part CMP-0061084-1, "Inductor, Shielded, Composite, 1 uH, 9 A, 0.0089 ohm, AEC-Q200 Grade 1, SMD"
L2 L3: library part CMP-0061086-1, "Inductor, Shielded, Composite, 1.5 uH, 8.1 A, 0.0151 ohm, AEC-Q200 Grade 1, SMD"
LBL1: library part CMP-0003625-1, "Thermal Transfer Printable Labels, 0.650\" W x 0.200\" H - 10,000 per roll"
LOGO1 LOGO2 LOGO3: library part IEC_HotSurface, "IEC 61010-1 Hot Surface Warning"
Logo2: library part CMP-0074839-1
Logo3: library part CMP-0074847-1, "FCC_disclaimer"
Q1: "MOSFET, N-CH, 40 V, 32 A, PowerPAK_SO-8L"
R1 R34 R35: "RES, 0, 5%, 0.1 W, 0603"
R2: "RES, 11.8 k, 1%, 0.1 W, 0603"
R3: "RES, 3.74 k, 0.1%, 0.1 W, 0603"
R4: "RES, 510, 0.1%, 0.1 W, 0603"
R5 R7 R8 R10 R12 R16 R18: "RES, 1.6 k, 5%, 0.1 W, 0603"
R6 R19: library part CMP-0026827-3, "RES, 10, 5%, 0.063 W, AEC-Q200 Grade 0, 0402"
R9 R21: library part CMP-0021990-4, "RES, 100 k, 1%, 0.1 W, AEC-Q200 Grade 0, 0603"
R11 R22: library part CMP-0021998-4, "RES, 10.0 k, 1%, 0.1 W, AEC-Q200 Grade 0, 0603"
R13: library part CMP-0022736-4, "RES, 100, 1%, 0.1 W, 0603"
R14 R23: library part CMP-0022933-5, "RES, 23.2 k, 1%, 0.1 W, 0603"
R15 R20: "RES, 4.70 k, 1%, 0.1 W, 0603"
R17 R24 R25: "RES, 10.0 k, 1%, 0.1 W, AEC-Q200 Grade 0, 0603"
R26 R27 R29 R30 R33: library part CMP-0020442-3, "RES, 0, 5%, 0.125 W, AEC-Q200 Grade 0, 0805"
R28 R32: library part CMP-0026926-3, "RES, 3.3, 5%, 0.063 W, AEC-Q200 Grade 0, 0402"
R31: "RES, 0.33, 1%, 0.1 W, 0603"
R57: "RES, 1.00 k, 0.01%, 0.063 W, 0603"
R58: "RES, 3.30 k, 1%, 0.1 W, 0603"
TP1 TP12: library part CMP-0055141-1, "Test Point, Miniature, Yellow, TH"
TP2 TP3 TP6 TP8 TP10: library part CMP-0055137-1, "Test Point, Miniature, Red, TH"
TP4 TP5 TP7 TP9 TP11: library part CMP-0055138-1, "Test Point, Miniature, Black, TH"
U1 U6: library part CMP-0076368-2, "Automotive 40V, 3.5A SIMPLE SWITCHER(R), 2.2MHz Step-Down Regulator with 40uA IQ, DDA0008E (SOIC-8)"
U2: library part CMP-0013281-4, "Low Iq Always ON Smart Diode Controller, DBV0006A (SOT-23-6)"
U3: library part CMP-0077252-2, "Automotive-Grade 2-A, High-Accuracy, Low-Noise, LDO Voltage Regulator, RGR0020A (VQFN-20)"
U4: "5.5-V, 2-A, 54mohm On-Resistance Load Switch, DBV0006A (SOT-23-6)"
U5: library part CMP-0074867-2, "Ambient Light Sensor (ALS), DNP0006A (USON-6)"
U8 U9 U10 U11: "24-Channel, Full Diagnostics, Constant-Current LED Driver with 7-Bit Dot Correction and 12-Bit PWM Dimming, DAP0038E (TSSOP-38)"
U12 U13 U14: library part CMP-0078396-2, "Automotive Grade 16-Channel, Full Diagnostics, Constant-Current LED Driver with 7-Bit Dot Correction and 12-Bit PWM Dimming, DAP0038E (TSSOP-38)"
U500: library part CMP-0066236-2, "Automotive Grade, 2.7V-Capable, 10 uA Analog Output Temperature Sensor, DCK0005A (SOT-SC70-5)"
Vbatt1: "Terminal Block, 2x1, Brass, TH"
ZZ1: library part CMP-0003616-3
ZZ2: library part CMP-0077236-1
ZZ3: library part CMP-0077237-1
ZZ4: library part CMP-0077238-1

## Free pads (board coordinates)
  round 60 hole 96 unplated: 0(297,685) 0(297,4850) 0(10770,685) 0(10770,4850)

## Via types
v1: diameter 20, hole 10, Top Layer to Bottom Layer, tented both sides, 504 vias
v2: diameter 26, hole 10, Top Layer to Bottom Layer, tented both sides, 472 vias
v3: diameter 19.68, hole 7.87, Top Layer to Bottom Layer, tented both sides, 205 vias
v4: diameter 34, hole 16, Top Layer to Bottom Layer, tented both sides, 2 vias
v5: diameter 19.68, hole 7.87, Top Layer to Bottom Layer, 1 vias

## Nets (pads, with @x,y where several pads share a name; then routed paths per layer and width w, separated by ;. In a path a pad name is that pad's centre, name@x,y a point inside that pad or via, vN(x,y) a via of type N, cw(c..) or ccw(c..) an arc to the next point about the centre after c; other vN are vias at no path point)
3V3: C7.1 C10.1 C11.1 C29.1 C500.1 J1.1 R2.2 R15.2 R17.2 R20.2 R24.2 TP8.1 U3.1 U3.19 U3.20 U4.1 U5.1 U500.1 U500.4 U500.5 | length 7211.2
  Top Layer w0: J1.1@9355.68,3983.33 J1.1@9356.72,3982.28
  Top Layer w20: R24.2@5929.86,3602.5 5931.33,3601.03 v2(5966.24,3601.03) ; U500.4@6105.31,3342.52 6228.35,3342.52 6342.36,3456.54 6354.06,3444.84 v2(8599.89,3444.84) ; v2(8492.13,4109.25) R15.2@8492.13,4162.4 8493.11,4163.39 R20.2@8493.11,4239.17
  Bottom Layer w20: v2(5953.74,3311.02) 5953.74,3603.35 6034.45,3684.06 TP8.1@6034.45,4159.45 v2@6034.45,5260.83 ; v2(6032.48,5262.8) v2@6034.45,5260.83 ; U5.1@6122.64,5260.24 6035.04,5260.24 v2@6034.45,5260.83 ; U5.1@6125.98,5256.4 6125.98,5161.42 6198.72,5161.42 R17.2@6256.97,5219.67 ; v2(8492.13,4109.25) 9229.75,4109.25 J1.1@9355.68,3983.33 9359.25,3979.75 9359.25,3519.69 9298.23,3458.66 9284.4,3444.84 v2(8599.89,3444.84)
3V3_LS: C9.1 C24.1 C25.1 C40.1 C41.1 C42.1 C43.1 C44.1 C45.1 C46.1 C47.1 C48.1 C49.1 C77.1 C88.1 R4.2 R57.2 R58.2 TP10.1 U4.6 U8.35 U9.35 U10.35 U11.35 U12.35 U13.35 U14.35 | length 19339.1
  Top Layer w10: U13.35@1731.2,1703.25 1830.21,1703.25 C41.1@1832.68,1700.79 1832.68,1804.13 v2(1815.94,1820.87) ; U10.35@4541.2,4333.25 4635.44,4333.25 C46.1@4642.75,4340.56 ; U11.35@4551.2,1693.25 4612.55,1693.25 C48.1@4645.67,1726.38 C49.1@4645.67,1786.42 4645.67,1809.06 v2(4616.14,1838.58)
  Top Layer w20: v2@1814.96,2014.76 2092.52,2292.32 2092.52,3755.91 ; 1818.9,4439.96 2005.91,4439.96 2092.52,4353.35 2092.52,3755.91 ; v2(4615.16,2000) 4615.16,3741.14 4600.39,3755.91 ; C46.1@4642.75,4340.56 4642.75,4435.07 4651.58,4443.9 4811.54,4443.9 4957.68,4297.76 4957.68,3746.32 ; TP10.1@5921.26,3834.65 5929.72,3834.65 6008.46,3755.91 ; R4.2@6009.45,3647.3 6009.45,3754.92 6008.46,3755.91 ; 7962.6,4323.82 7976.38,4323.82 C77.1@8018.7,4366.14 8020.67,4368.11 8020.67,4413.39 8037.4,4430.12 C88.1@8153.54,4430.12 8348.6,4430.12 8374.02,4404.7 8374.02,3757.87 8375.98,3755.91 ; 7990.16,1703.74 C43.1@8042.32,1742.13 8047.24,1747.05 8047.24,1785.43 8062.99,1801.18 R57.2@8359.25,1801.18 ; R57.2@8359.25,1803.15 v2(9473.43,1803.15) ; v2(9815.94,3209.65) v2(9471.46,3209.65) 9472.44,3210.63 9472.44,3401.57 9118.11,3755.91 8375.98,3755.91 ; 2092.52,3755.91 4600.39,3755.91 ; 4600.39,3755.91 6008.46,3755.91 ; 6008.46,3755.91 8375.98,3755.91
  Bottom Layer w20: v2(1815.94,1820.87) v2(1815.94,2016.73) ; v2(4615.16,2000) v2(4616.14,1838.58) ; v2(9471.46,3209.65) 9472.44,1921.26 9473.43,1920.28 v2(9473.43,1803.15) v2@9474.41,1802.17 ; v2(9815.94,3209.65) 10215.55,3209.65 v2(10277.56,3159.45)
ANODE: C3.1 C6.1 D148.1 Q1.1 Q1.2 Q1.3 R1.1 U2.3 U2.6 Vbatt1.1
BLANK: J1.2 U8.36 U9.36 U10.36 U11.36 U12.36 U13.36 U14.36 | length 17777.1
  Top Layer w10: U12.36@1721.2,4348.84 1756.32,4348.84 1773.71,4366.23 v2(1773.62,4462.6) ; U13.36@1731.2,1728.84 1759.82,1728.84 1779.53,1748.55 v2(1779.53,1879.92) ; v2(4463.58,4464.57) 4463.58,4390.75 4495.49,4358.84 U10.36@4541.2,4358.84 4584.24,4358.84 4589.78,4364.39 v2(4593.73,4364.39) ; U11.36@4551.2,1718.84 4593.16,1718.84 4602.36,1728.04 4602.36,1783.46 v2(4582.68,1803.15) ; v2(5086.61,4445.87) v2(7127.95,4445.87) ; v2@7821.85,4451.77 v2(7821.85,4445.87) 7821.85,4398.62 7871.63,4348.84 U9.36@7911.2,4348.84 7945.3,4348.84 v2(7967.52,4371.06) ; U8.36@7931.7,1728.35 U8.36@7931.2,1728.84 7971.95,1728.84 7985.24,1742.13 7985.24,1878.94 v2(7987.2,1880.91) ; J1.2@9255.68,3983.33 9255.68,3947.48 10162.69,3040.46 U14.36@10191.32,3040.46
  PWR w10: v2(1773.62,4462.6) 1785.43,4450.79 4449.8,4450.79 v2(4463.58,4464.57) 4533.46,4534.45 4991.14,4534.45 v2(5086.61,4445.87) ; v2(7127.95,4445.87) v2(7821.85,4445.87) ; v2(7967.52,4371.06) 9002.95,4371.06 9255.91,4118.11 9255.91,3983.56 J1.2@9255.68,3983.33
  Bottom Layer w10: v2(1773.62,4462.6) 1773.71,1885.74 v2(1779.53,1879.92) ; v2(4582.68,1803.15) 4582.68,3944.76 4593.73,3955.81 v2(4593.73,4364.39) ; v2(7967.52,4371.06) 7967.52,3078.74 7980.32,3065.94 7980.32,1887.8 v2(7987.2,1880.91)
Buck1_4V: C30.1 D1.2 D2.2 D3.2 D4.2 D5.2 D6.2 D7.2 D8.2 D9.2 D10.2 D11.2 D12.2 D13.2 D14.2 D15.2 D16.2 D17.2 D18.2 D19.2 D20.2 D21.2 D22.2 D23.2 D24.2 D25.2 D26.2 D27.2 D28.2 D29.2 D30.2 D31.2 D32.2 D33.2 D34.2 D35.2 D36.2 D37.2 D38.2 D39.2 D40.2 D41.2 D42.2 D43.2 D44.2 D45.2 D46.2 D47.2 D48.2 D129.2 D130.2 D131.2 D132.2 D133.2 D134.2 D135.2 D136.2 D137.2 D138.2 D139.2 D140.2 D141.2 D142.2 D143.2 D144.2 R30.2 TP3.1 U3.14 U3.15 U3.16 U3.17 U8.38 U9.38 U14.38 | length 637.1
  PWR w25: v2@5656.2,3359.25 6293.31,3359.25
  other v2: 6934.06,547.24 6363.19,550.2 7493.11,552.17 8053.15,553.15 10338.58,554.13 9753.94,555.12 8613.19,557.09 9184.06,558.07 6363.56,1209.71 6933.56,1209.71 7493.56,1209.71 8053.56,1209.71 8613.56,1209.71 9183.56,1209.71 9753.56,1209.71 10336.56,1209.71 7931.1,1841.54 9753.94,1855.32 10334.65,1859.25 6934.06,1860.24 8053.15,1860.24 6364.17,1864.17 7494.09,1869.09 9184.06,1871.06 8611.22,1874.02 6362.2,2514.76 6934.06,2517.72 8613.19,2518.7 10330.71,2518.7 7495.08,2520.67 9751.97,2520.67 9182.09,2521.65 8052.17,2522.64 10192.91,3139.76 9752.95,3153.54 10328.74,3156.5 7493.11,3163.39 6933.07,3165.35 8614.17,3170.28 6363.19,3171.26 7591.42,3171.14 7627.95,3171.26 7664.49,3171.38 9183.07,3173.23 8055.12,3176.18 7591.42,3209.47 7627.95,3209.59 7664.49,3209.7 7591.42,3247.8 7627.95,3247.92 7664.49,3248.03 7702.81,3248.03 7741.14,3248.03 5599.11,3325.44 5627.66,3325.44 5656.2,3325.44 5599.11,3353.98 5627.66,3353.98 5656.2,3353.98 8614.17,3835.63 6933.07,3837.6 9753.94,3837.6 6363.19,3839.57 8053.15,3839.57 7494.09,3840.55 9184.06,3842.52 10326.77,3842.52 7913.39,4446.85 9184.06,4473.43 10323.82,4473.43 7494.09,4474.41 9752.95,4474.41 6364.17,4475.39 8053.15,4475.39 8613.19,4477.36 6933.07,4481.3 9754.37,5145.25 10324.37,5147.25 6364.25,5147.64 6934.25,5147.64 7494.25,5147.64 8054.25,5147.64 8614.25,5147.64 9184.25,5147.64
buck2_4V: D49.2 D50.2 D51.2 D52.2 D53.2 D54.2 D55.2 D56.2 D57.2 D58.2 D59.2 D60.2 D61.2 D62.2 D63.2 D64.2 D65.2 D66.2 D67.2 D68.2 D69.2 D70.2 D71.2 D72.2 D73.2 D74.2 D75.2 D76.2 D77.2 D78.2 D79.2 D80.2 D81.2 D82.2 D83.2 D84.2 D85.2 D86.2 D87.2 D88.2 D89.2 D90.2 D91.2 D92.2 D93.2 D94.2 D95.2 D96.2 D97.2 D98.2 D99.2 D100.2 D101.2 D102.2 D103.2 D104.2 D105.2 D106.2 D107.2 D108.2 D109.2 D110.2 D111.2 D112.2 D113.2 D114.2 D115.2 D116.2 D117.2 D118.2 D119.2 D120.2 D121.2 D122.2 D123.2 D124.2 D125.2 D126.2 D127.2 D128.2 R33.2 TP6.1 U10.38 U11.38 U12.38 U13.38 | length 594.2
  Bottom Layer w10: D75.2@3539.78,2470.06 3582.68,2427.17 v2(3582.68,2343.5) ; v2(4113.19,4483.27) 4119.49,4489.57 4473.94,4489.57 4474.33,4489.17 4508.86,4489.17 4539.37,4458.66 v2(4539.37,4451.77) ; 5767,5174 5768,5175
  other v2: 744.09,544.29 3554.13,550.2 1304.13,551.18 4114.17,551.18 2424.21,552.17 2983.27,552.17 5243.11,552.17 4673.23,553.15 1863.19,559.06 5804.13,560.04 743.56,1199.71 1303.56,1209.71 1863.56,1209.71 2423.56,1209.71 2983.56,1209.71 3553.56,1209.71 4113.56,1209.71 4673.56,1209.71 5243.56,1209.71 5803.56,1209.71 1736.22,1822.83 4545.28,1837.6 743.11,1848.43 4114.17,1863.19 4674.21,1865.16 5803.15,1865.16 5244.09,1866.14 1303.15,1867.13 2983.27,1874.02 1866.14,1875 2430.12,1875.98 3554.13,1875.98 3712.73,2280.51 3751.06,2280.51 3789.39,2280.51 3827.72,2280.51 3866.05,2280.51 3775.61,2315.89 3813.94,2315.89 3852.27,2315.89 3775.61,2354.21 3813.94,2354.21 3852.27,2354.21 2984.25,2514.76 746.06,2516.73 5243.11,2516.73 2424.21,2518.7 4674.21,2518.7 4113.19,2519.68 5804.13,2519.68 1303.15,2520.67 1868.11,2523.62 1863.19,3166.34 5803.15,3166.34 743.11,3168.31 4114.17,3168.31 1303.15,3169.29 5243.11,3169.29 4673.23,3170.28 2423.23,3173.23 2983.27,3177.17 3553.15,3181.1 744.09,3824.8 1863.19,3829.72 2423.23,3831.69 2984.25,3831.69 4673.23,3833.66 4114.17,3835.63 3554.13,3836.61 1306.1,3838.58 5802.17,3838.58 5240.16,3843.5 1721.46,4450.79 4673.23,4475.39 2984.25,4477.36 5244.09,4477.36 744.09,4478.35 5803.15,4478.35 2424.21,4479.33 1863.19,4481.3 3554.13,4482.28 1304.13,4483.27 744.25,5147.64 1304.25,5147.64 1864.25,5147.63 2424.25,5147.64 2984.25,5147.64 3554.25,5147.64 4114.25,5147.64 4674.25,5147.64 5244.25,5147.64 5804.25,5147.64
ENABLE: J1.3 R25.2 U4.3 | length 3580.7
  Top Layer w10: U4.3@6129.2,3465.42 6189.55,3465.41 R25.2@6199.94,3475.8 6199.94,3478.54 6211.56,3490.16 6211.86,3489.86 v2(8652.47,3489.86)
  Bottom Layer w10: v2(8652.47,3489.86) 9130.61,3489.86 9232.28,3591.54 9232.28,3906.72 J1.3@9155.68,3983.33
ERR: D01.2 J2.5 R58.1 U8.20 U9.20 U10.20 U11.20 U12.20 U13.20 U14.20 | length 20276.5
  Top Layer w10: v2(1720.47,3901.57) 1720.47,3938.67 U12.20@1721.2,3939.4 ; U13.20@1731.2,1319.4 1731.3,1319.3 v2(1731.3,1274.61) ; U10.20@4541.2,3949.4 4541.2,3940.71 4541.34,3940.71 v2(4541.34,3911.42) ; U11.20@4551.2,1309.4 4551.2,1299.44 4552.17,1299.44 v2(4552.17,1267.72) ; v2(4974.41,1258.86) 5321.06,1605.51 5927.15,1605.51 6286.42,1606.9 6811.41,1606.9 v2(7136.81,1281.5) ; v2(5037.4,3926.18) 5062.01,3901.57 v2(7914.37,3901.57) 7914.37,3936.22 U9.20@7912.4,3938.19 ; U9.20@7911.2,3939.4 U9.20@7912.4,3938.19 ; U8.20@7931.2,1319.4 7931.2,1314.71 U8.20@7932.09,1314.71 ; v2(7932.09,1282.48) U8.20@7932.09,1314.71 ; D01.2@8301.18,1650.59 8302.17,1649.61 8302.17,1408.46 8213.1,1319.4 8018.6,1319.4 8013.92,1314.71 U8.20@7932.09,1314.71 ; R58.1@8319.88,4363.19 8319.88,4093.5 8138.78,3912.4 7980.31,3912.4 7954.72,3937.99 U9.20@7912.4,3938.19 ; J2.5@8855,2184 8855,2112.01 8854.6,2111.6 8940.87,2025.33 9347.58,2025.33 9909.85,2587.6 v2(10193.9,2587.6) 10193.9,2628.43 U14.20@10191.32,2631.01
  PWR w10: v2(1720.47,3901.57) 4531.5,3901.57 v2(4541.34,3911.42) 5022.64,3911.42 v2(5037.4,3926.18) ; v2(1731.3,1274.61) 1743.11,1262.8 1810.04,1262.8 4513.78,1259.84 4544.29,1259.84 v2(4552.17,1267.72) 4561.02,1258.86 v2(4974.41,1258.86) ; v2(7136.81,1281.5) 7410.76,1281.5 7416.16,1276.1 7440.18,1276.1 7445.58,1281.5 7916.56,1281.5 7923.83,1274.23 v2(7932.09,1282.48) ; v2(7914.37,3901.57) 7922.24,3901.57 7922.24,3899.61 8460.91,3899.61
  Bottom Layer w10: v2(1720.47,3901.57) 1688.98,3870.08 1688.98,1283.46 1697.83,1274.61 v2(1731.3,1274.61) ; v2(8303.33,1582.67) 8511.68,1791.02 8511.68,1982.06 8606.65,2077.03 8820.02,2077.03 8855,2112.01 J2.5@8855,2184
GATE: Q1.4 U2.5 | length 181.6
  Top Layer w10: Q1.4@6139.95,765.27 6139.95,769.12 6277.14,769.12 6281.5,764.76 U2.5@6281.5,730.31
